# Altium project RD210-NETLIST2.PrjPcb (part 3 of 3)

## Sheet 10.SchDoc
size 609 x 444 mm
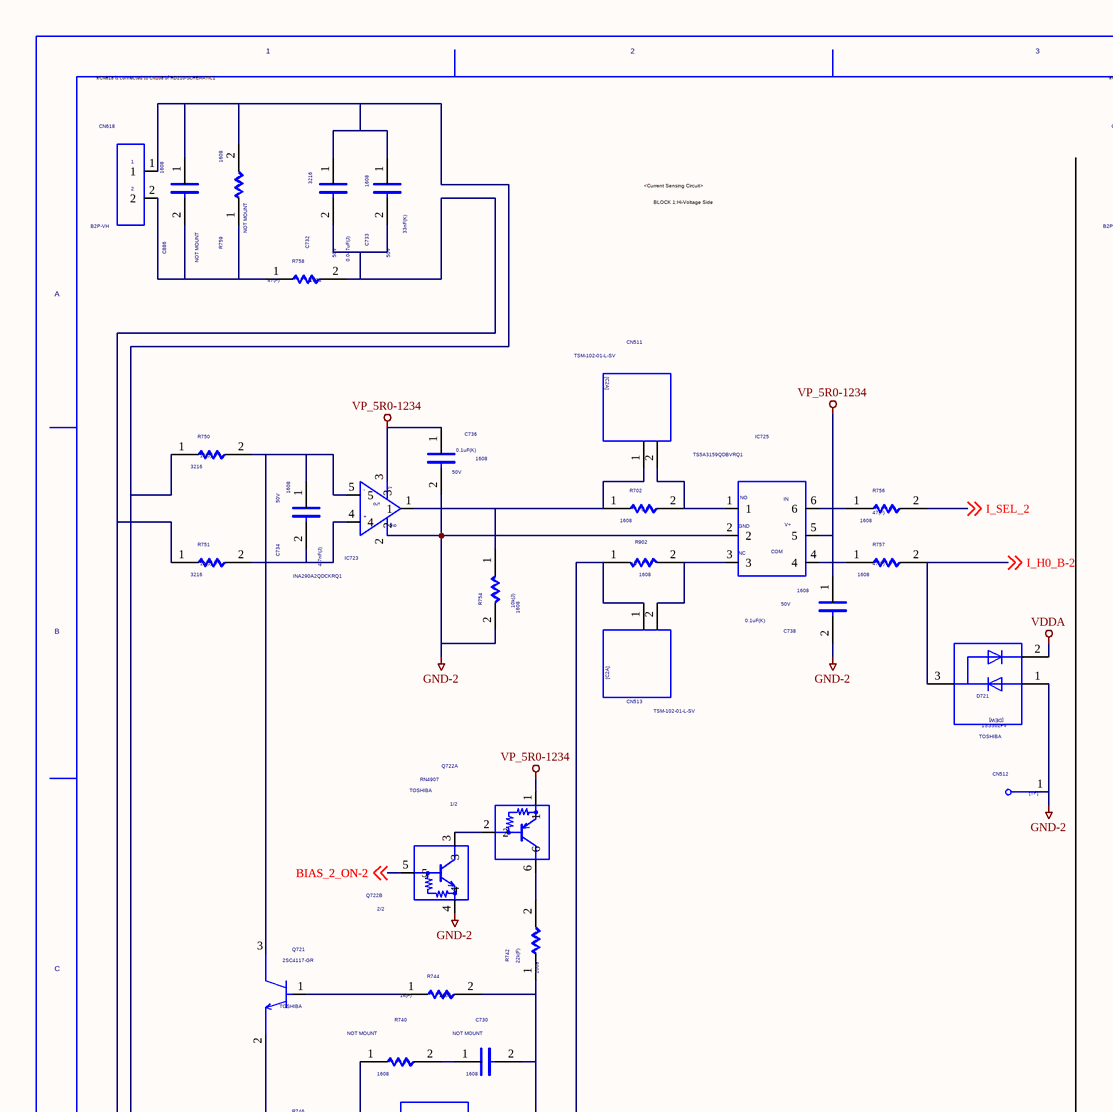
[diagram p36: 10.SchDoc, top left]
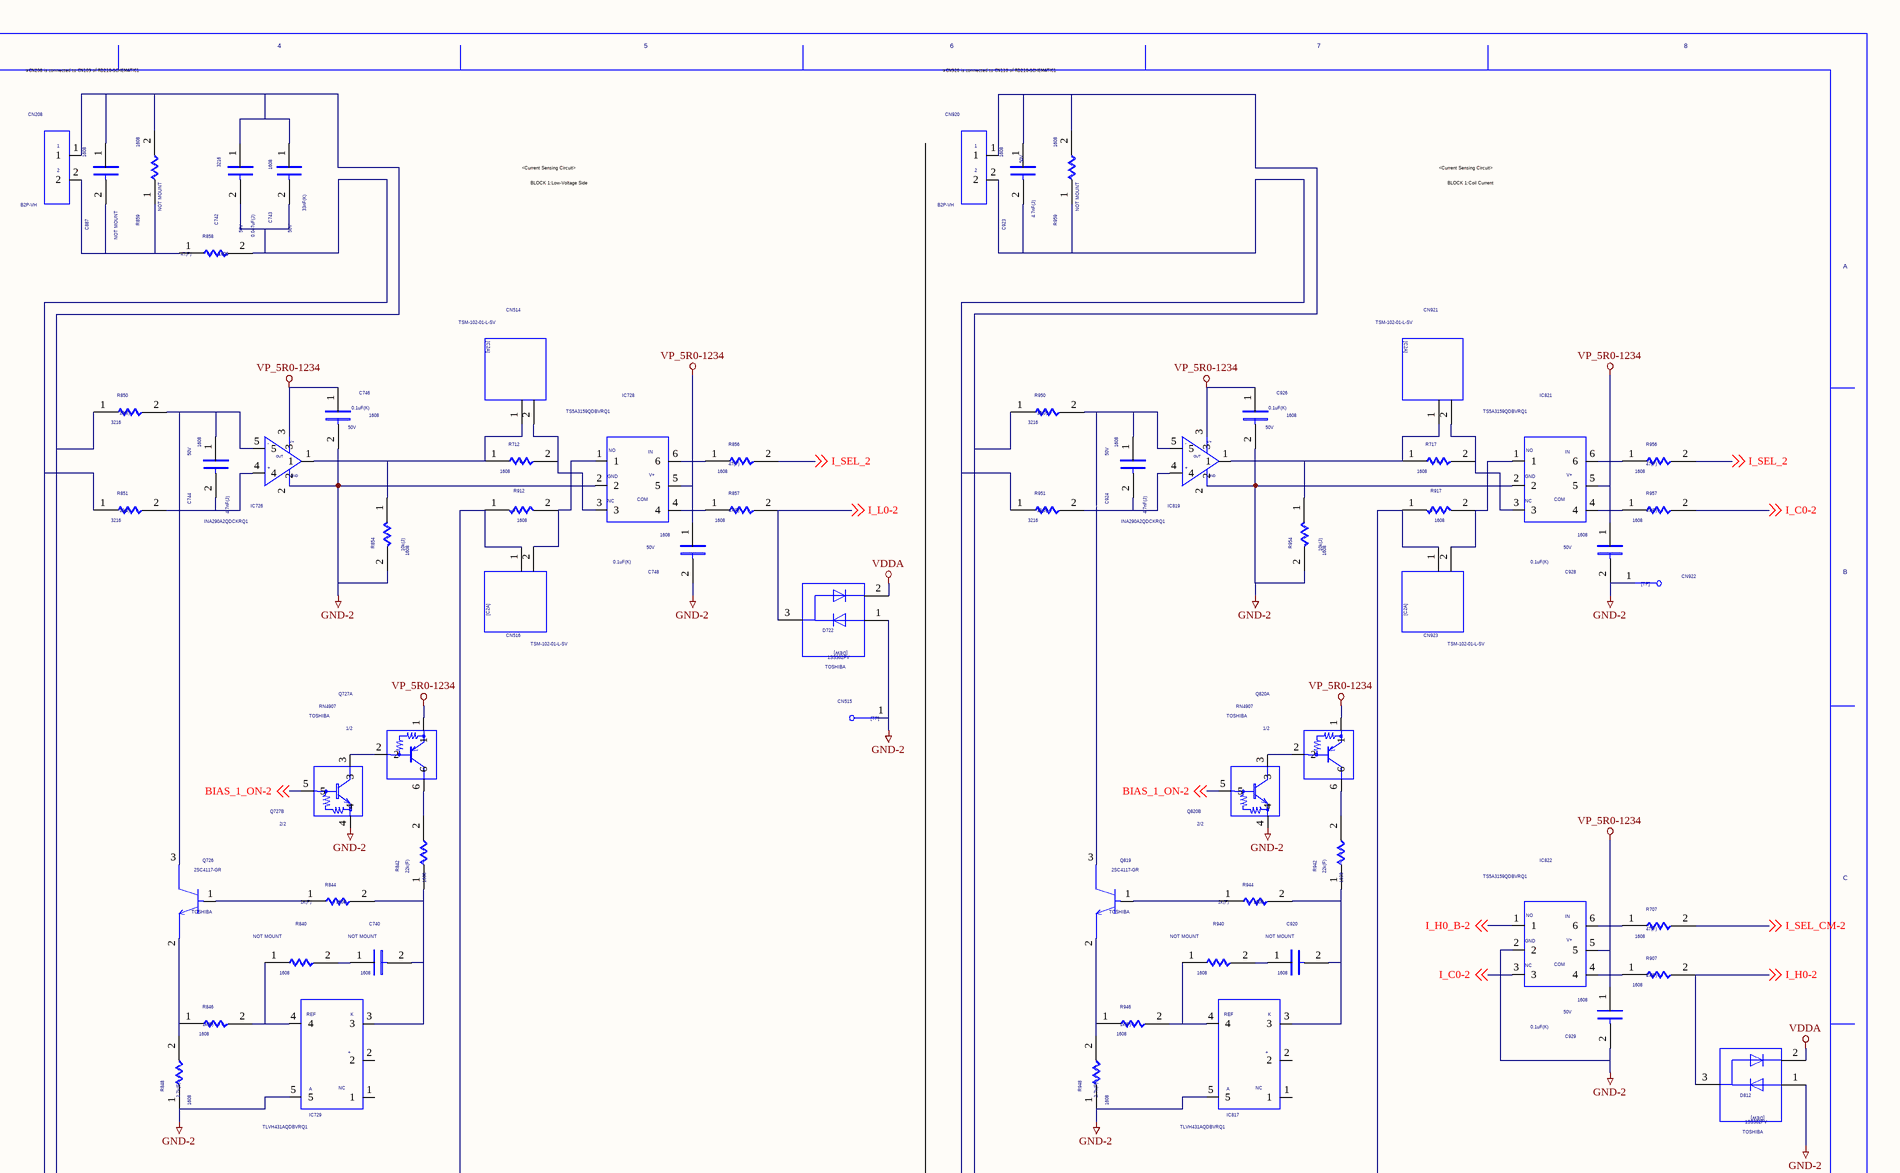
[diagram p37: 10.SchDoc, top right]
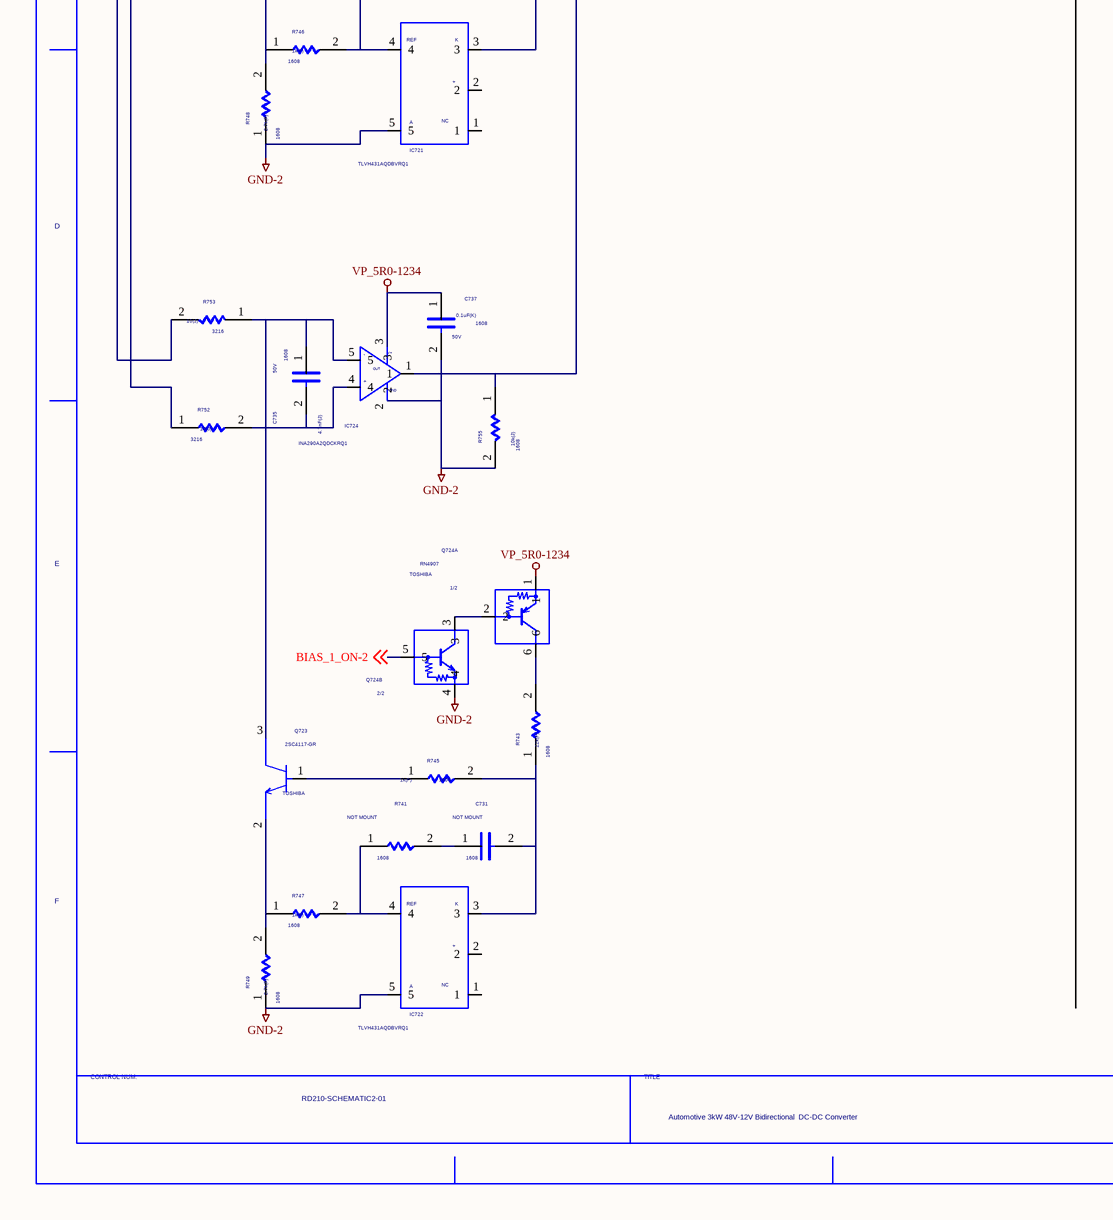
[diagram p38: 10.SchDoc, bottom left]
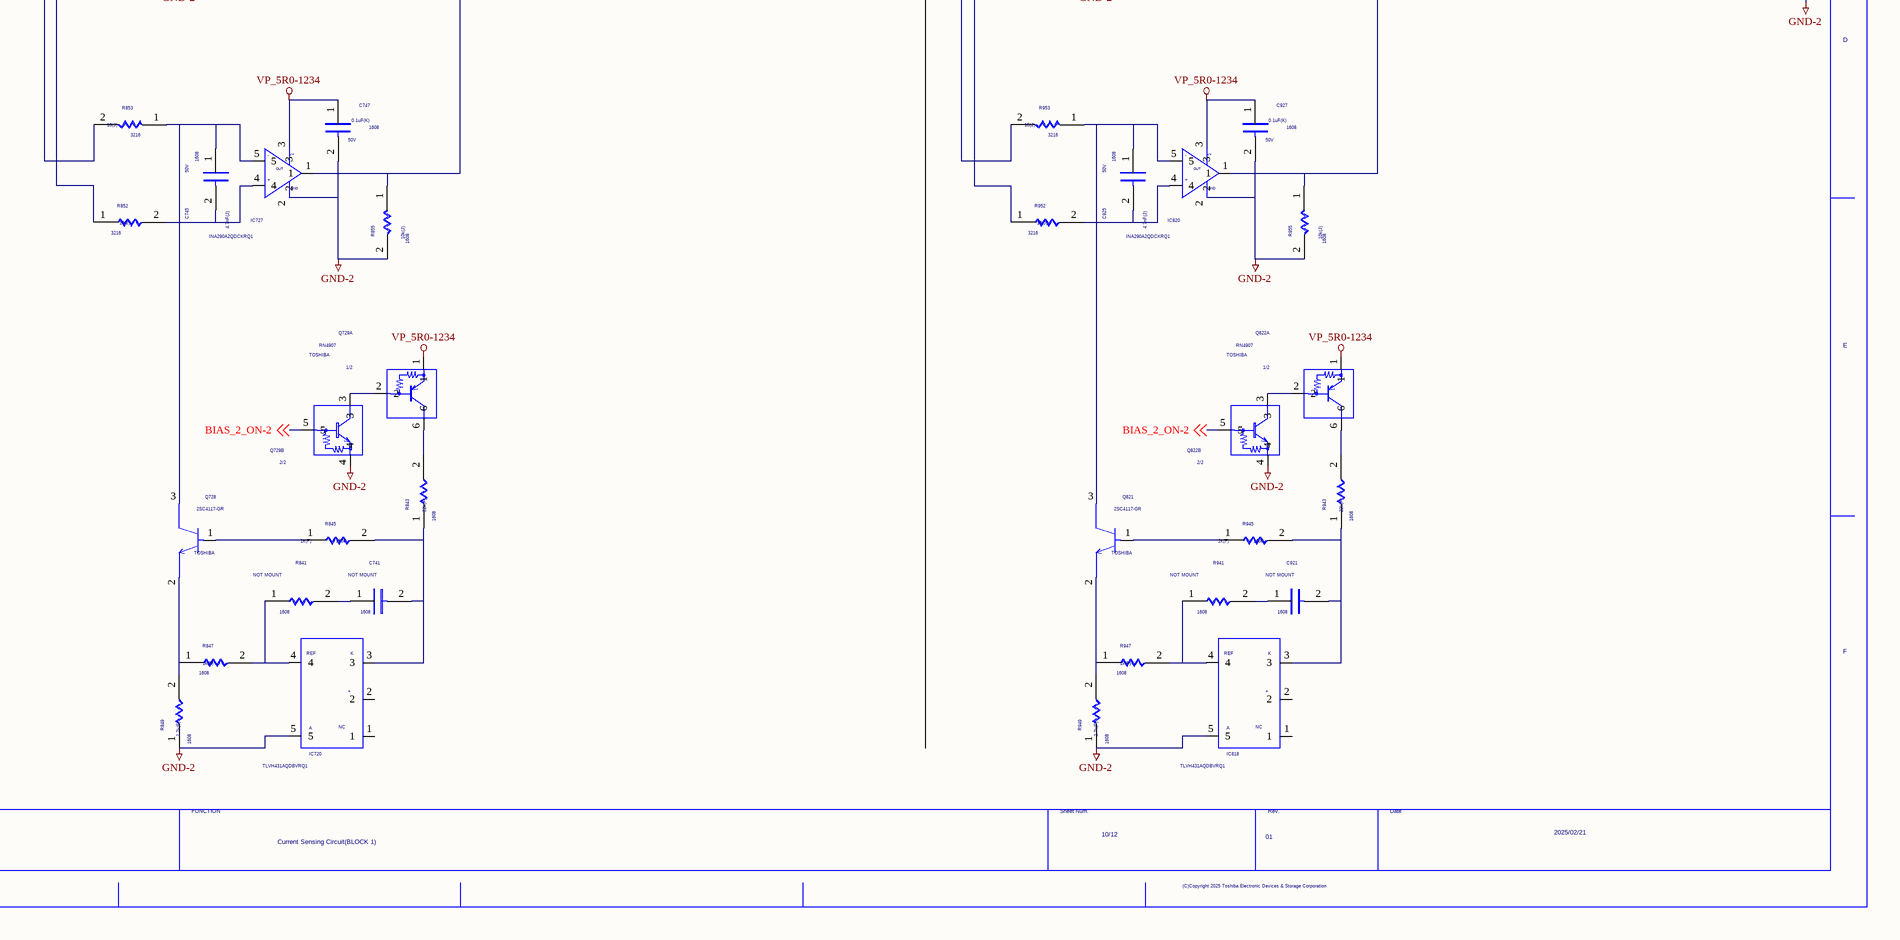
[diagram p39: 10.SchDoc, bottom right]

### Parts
(Parts that share a designator on the sheet are numbered #1, #2 ... from top to bottom, then left to right.)
C730  NOTMOUNT: NOT MOUNT  SIZECODESMD: 1608  (hidden comment: C)
C731  NOTMOUNT: NOT MOUNT  SIZECODESMD: 1608  (hidden comment: C)
C732  VAL1: 0.047uF(J)  VAL2: 50V  SIZECODESMD: 3216  (hidden comment: C)
C733  VAL1: 33nF(K)  VAL2: 50V  SIZECODESMD: 1608  (hidden comment: C)
C734  VAL1: 4.7nF(J)  VAL2: 50V  SIZECODESMD: 1608  (hidden comment: C)
C735  VAL1: 4.7nF(J)  VAL2: 50V  SIZECODESMD: 1608  (hidden comment: C)
C736  VAL1: 0.1uF(K)  VAL2: 50V  SIZECODESMD: 1608  (hidden comment: C)
C737  VAL1: 0.1uF(K)  VAL2: 50V  SIZECODESMD: 1608  (hidden comment: C)
C738  VAL1: 0.1uF(K)  VAL2: 50V  SIZECODESMD: 1608  (hidden comment: C)
C740  NOTMOUNT: NOT MOUNT  SIZECODESMD: 1608  (hidden comment: C)
C741  NOTMOUNT: NOT MOUNT  SIZECODESMD: 1608  (hidden comment: C)
C742  VAL1: 0.047uF(J)  VAL2: 50V  SIZECODESMD: 3216  (hidden comment: C)
C743  VAL1: 33nF(K)  VAL2: 50V  SIZECODESMD: 1608  (hidden comment: C)
C744  VAL1: 4.7nF(J)  VAL2: 50V  SIZECODESMD: 1608  (hidden comment: C)
C745  VAL1: 4.7nF(J)  VAL2: 50V  SIZECODESMD: 1608  (hidden comment: C)
C746  VAL1: 0.1uF(K)  VAL2: 50V  SIZECODESMD: 1608  (hidden comment: C)
C747  VAL1: 0.1uF(K)  VAL2: 50V  SIZECODESMD: 1608  (hidden comment: C)
C748  VAL1: 0.1uF(K)  VAL2: 50V  SIZECODESMD: 1608  (hidden comment: C)
C886  NOTMOUNT: NOT MOUNT  SIZECODESMD: 1608  (hidden comment: C)
C887  NOTMOUNT: NOT MOUNT  SIZECODESMD: 1608  (hidden comment: C)
C920  NOTMOUNT: NOT MOUNT  SIZECODESMD: 1608  (hidden comment: C)
C921  NOTMOUNT: NOT MOUNT  SIZECODESMD: 1608  (hidden comment: C)
C923  VAL1: 4.7nF(J)  VAL2: 50V  SIZECODESMD: 1608  (hidden comment: C)
C924  VAL1: 4.7nF(J)  VAL2: 50V  SIZECODESMD: 1608  (hidden comment: C)
C925  VAL1: 4.7nF(J)  VAL2: 50V  SIZECODESMD: 1608  (hidden comment: C)
C926  VAL1: 0.1uF(K)  VAL2: 50V  SIZECODESMD: 1608  (hidden comment: C)
C927  VAL1: 0.1uF(K)  VAL2: 50V  SIZECODESMD: 1608  (hidden comment: C)
C928  VAL1: 0.1uF(K)  VAL2: 50V  SIZECODESMD: 1608  (hidden comment: C)
C929  VAL1: 0.1uF(K)  VAL2: 50V  SIZECODESMD: 1608  (hidden comment: C)
CN208  B2P-VH
CN511  VAL3: TSM-102-01-L-SV  (hidden comment: C2A)
CN512  TP  (value not drawn)
CN513  VAL3: TSM-102-01-L-SV  (hidden comment: C2A)
CN514  VAL3: TSM-102-01-L-SV  (hidden comment: C2A)
CN515  TP  (value not drawn)
CN516  VAL3: TSM-102-01-L-SV  (hidden comment: C2A)
CN618  B2P-VH
CN920  B2P-VH
CN921  VAL3: TSM-102-01-L-SV  (hidden comment: C2A)
CN922  TP  (value not drawn)
CN923  VAL3: TSM-102-01-L-SV  (hidden comment: C2A)
D721  USERCOMPTEXT3: TOSHIBA  VAL3: 1SS362FV  (hidden comment: DEW)
D722  USERCOMPTEXT3: TOSHIBA  VAL3: 1SS362FV  (hidden comment: DEW)
D812  USERCOMPTEXT3: TOSHIBA  VAL3: 1SS362FV  (hidden comment: DEW)
IC720  TLVH431AQDBVRQ1
IC721  TLVH431AQDBVRQ1
IC722  TLVH431AQDBVRQ1
IC723  INA290A2QDCKRQ1
IC724  INA290A2QDCKRQ1
IC725  TS5A3159QDBVRQ1
IC726  INA290A2QDCKRQ1
IC727  INA290A2QDCKRQ1
IC728  TS5A3159QDBVRQ1
IC729  TLVH431AQDBVRQ1
IC817  TLVH431AQDBVRQ1
IC818  TLVH431AQDBVRQ1
IC819  INA290A2QDCKRQ1
IC820  INA290A2QDCKRQ1
IC821  TS5A3159QDBVRQ1
IC822  TS5A3159QDBVRQ1
Q721  USERCOMPTEXT3: TOSHIBA  VAL3: 2SC4117-GR  (hidden comment: TRN)
Q722  USERCOMPTEXT1: 1/2  USERCOMPTEXT3: TOSHIBA  VAL3: RN4907  (hidden comment: RN4907_Q2)  (parts A,B of 2)
Q723  USERCOMPTEXT3: TOSHIBA  VAL3: 2SC4117-GR  (hidden comment: TRN)
Q724  USERCOMPTEXT1: 1/2  USERCOMPTEXT3: TOSHIBA  VAL3: RN4907  (hidden comment: RN4907_Q2)  (parts A,B of 2)
Q726  USERCOMPTEXT3: TOSHIBA  VAL3: 2SC4117-GR  (hidden comment: TRN)
Q727  USERCOMPTEXT1: 1/2  USERCOMPTEXT3: TOSHIBA  VAL3: RN4907  (hidden comment: RN4907_Q2)  (parts A,B of 2)
Q728  USERCOMPTEXT3: TOSHIBA  VAL3: 2SC4117-GR  (hidden comment: TRN)
Q729  USERCOMPTEXT1: 1/2  USERCOMPTEXT3: TOSHIBA  VAL3: RN4907  (hidden comment: RN4907_Q2)  (parts A,B of 2)
Q819  USERCOMPTEXT3: TOSHIBA  VAL3: 2SC4117-GR  (hidden comment: TRN)
Q820  USERCOMPTEXT1: 1/2  USERCOMPTEXT3: TOSHIBA  VAL3: RN4907  (hidden comment: RN4907_Q2)  (parts A,B of 2)
Q821  USERCOMPTEXT3: TOSHIBA  VAL3: 2SC4117-GR  (hidden comment: TRN)
Q822  USERCOMPTEXT1: 1/2  USERCOMPTEXT3: TOSHIBA  VAL3: RN4907  (hidden comment: RN4907_Q2)  (parts A,B of 2)
R702  VAL1: 0  SIZECODESMD: 1608  (hidden comment: R)
R707  VAL1: 47(F)  SIZECODESMD: 1608  (hidden comment: R)
R712  VAL1: 0  SIZECODESMD: 1608  (hidden comment: R)
R717  VAL1: 0  SIZECODESMD: 1608  (hidden comment: R)
R740  NOTMOUNT: NOT MOUNT  SIZECODESMD: 1608  (hidden comment: R)
R741  NOTMOUNT: NOT MOUNT  SIZECODESMD: 1608  (hidden comment: R)
R742  VAL1: 22k(F)  SIZECODESMD: 1608  (hidden comment: R)
R743  VAL1: 22k(F)  SIZECODESMD: 1608  (hidden comment: R)
R744  VAL1: 1k(F)  SIZECODESMD: 1608  (hidden comment: R)
R745  VAL1: 1k(F)  SIZECODESMD: 1608  (hidden comment: R)
R746  VAL1: 1k(F)  SIZECODESMD: 1608  (hidden comment: R)
R747  VAL1: 1k(F)  SIZECODESMD: 1608  (hidden comment: R)
R748  VAL1: 2.7k(F)  SIZECODESMD: 1608  (hidden comment: R)
R749  VAL1: 2.7k(F)  SIZECODESMD: 1608  (hidden comment: R)
R750  VAL1: 10(J)  SIZECODESMD: 3216  (hidden comment: R)
R751  VAL1: 10(J)  SIZECODESMD: 3216  (hidden comment: R)
R752  VAL1: 10(J)  SIZECODESMD: 3216  (hidden comment: R)
R753  VAL1: 10(J)  SIZECODESMD: 3216  (hidden comment: R)
R754  VAL1: 10k(J)  SIZECODESMD: 1608  (hidden comment: R)
R755  VAL1: 10k(J)  SIZECODESMD: 1608  (hidden comment: R)
R756  VAL1: 47(F)  SIZECODESMD: 1608  (hidden comment: R)
R757  VAL1: 47(F)  SIZECODESMD: 1608  (hidden comment: R)
R758  VAL1: 47(F)  SIZECODESMD: 1608  (hidden comment: R)
R759  NOTMOUNT: NOT MOUNT  SIZECODESMD: 1608  (hidden comment: R)
R840  NOTMOUNT: NOT MOUNT  SIZECODESMD: 1608  (hidden comment: R)
R841  NOTMOUNT: NOT MOUNT  SIZECODESMD: 1608  (hidden comment: R)
R842  VAL1: 22k(F)  SIZECODESMD: 1608  (hidden comment: R)
R843  VAL1: 22k(F)  SIZECODESMD: 1608  (hidden comment: R)
R844  VAL1: 1k(F)  SIZECODESMD: 1608  (hidden comment: R)
R845  VAL1: 1k(F)  SIZECODESMD: 1608  (hidden comment: R)
R846  VAL1: 1k(F)  SIZECODESMD: 1608  (hidden comment: R)
R847  VAL1: 1k(F)  SIZECODESMD: 1608  (hidden comment: R)
R848  VAL1: 2.7k(F)  SIZECODESMD: 1608  (hidden comment: R)
R849  VAL1: 2.7k(F)  SIZECODESMD: 1608  (hidden comment: R)
R850  VAL1: 10(J)  SIZECODESMD: 3216  (hidden comment: R)
R851  VAL1: 10(J)  SIZECODESMD: 3216  (hidden comment: R)
R852  VAL1: 10(J)  SIZECODESMD: 3216  (hidden comment: R)
R853  VAL1: 10(J)  SIZECODESMD: 3216  (hidden comment: R)
R854  VAL1: 10k(J)  SIZECODESMD: 1608  (hidden comment: R)
R855  VAL1: 10k(J)  SIZECODESMD: 1608  (hidden comment: R)
R856  VAL1: 47(F)  SIZECODESMD: 1608  (hidden comment: R)
R857  VAL1: 47(F)  SIZECODESMD: 1608  (hidden comment: R)
R858  VAL1: 47(F)  SIZECODESMD: 1608  (hidden comment: R)
R859  NOTMOUNT: NOT MOUNT  SIZECODESMD: 1608  (hidden comment: R)
R902  VAL1: 0  SIZECODESMD: 1608  (hidden comment: R)
R907  VAL1: 47(F)  SIZECODESMD: 1608  (hidden comment: R)
R912  VAL1: 0  SIZECODESMD: 1608  (hidden comment: R)
R917  VAL1: 0  SIZECODESMD: 1608  (hidden comment: R)
R940  NOTMOUNT: NOT MOUNT  SIZECODESMD: 1608  (hidden comment: R)
R941  NOTMOUNT: NOT MOUNT  SIZECODESMD: 1608  (hidden comment: R)
R942  VAL1: 22k(F)  SIZECODESMD: 1608  (hidden comment: R)
R943  VAL1: 22k(F)  SIZECODESMD: 1608  (hidden comment: R)
R944  VAL1: 1k(F)  SIZECODESMD: 1608  (hidden comment: R)
R945  VAL1: 1k(F)  SIZECODESMD: 1608  (hidden comment: R)
R946  VAL1: 1k(F)  SIZECODESMD: 1608  (hidden comment: R)
R947  VAL1: 1k(F)  SIZECODESMD: 1608  (hidden comment: R)
R948  VAL1: 2.7k(F)  SIZECODESMD: 1608  (hidden comment: R)
R949  VAL1: 2.7k(F)  SIZECODESMD: 1608  (hidden comment: R)
R950  VAL1: 10(J)  SIZECODESMD: 3216  (hidden comment: R)
R951  VAL1: 10(J)  SIZECODESMD: 3216  (hidden comment: R)
R952  VAL1: 10(J)  SIZECODESMD: 3216  (hidden comment: R)
R953  VAL1: 10(J)  SIZECODESMD: 3216  (hidden comment: R)
R954  VAL1: 10k(J)  SIZECODESMD: 1608  (hidden comment: R)
R955  VAL1: 10k(J)  SIZECODESMD: 1608  (hidden comment: R)
R956  VAL1: 47(F)  SIZECODESMD: 1608  (hidden comment: R)
R957  VAL1: 47(F)  SIZECODESMD: 1608  (hidden comment: R)
R959  NOTMOUNT: NOT MOUNT  SIZECODESMD: 1608  (hidden comment: R)
U?#10  DATE: 2025/02/21  DRAWINGNUMBER: RD210-SCHEMATIC2-01  TITLE: Automotive 3kW 48V-12V Bidirectional / DC-DC Converter  FUNCTION: Current Sensing Circuit(BLOCK 1)  SHEETNUMBER: 10/12  REVISION: 01  (hidden comment: WAKU_DEF_A3)

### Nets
GND-2: C736.2 C737.2 C738.2 C746.2 C747.2 C748.2 C926.2 C927.2 C928.2 C929.2 CN512.1 CN515.1 CN922.1 D721.1(A) D722.1(A) D812.1(A) IC720.5 IC721.5 IC722.5 IC723.2 IC724.2 IC725.2 IC726.2 IC727.2 IC728.2 IC729.5 IC817.5 IC818.5 IC819.2 IC820.2 IC821.2 IC822.2 Q722.4 Q724.4 Q727.4 Q729.4 Q820.4 Q822.4 R748.1 R749.1 R754.2 R755.2 R848.1 R849.1 R854.2 R855.2 R948.1 R949.1 R954.2 R955.2
VDDA: D721.2(C) D722.2(C) D812.2(C)
VP_5R0-1234: C736.1 C737.1 C738.1 C746.1 C747.1 C748.1 C926.1 C927.1 C928.1 C929.1 IC723.3 IC724.3 IC725.5 IC726.3 IC727.3 IC728.5 IC819.3 IC820.3 IC821.5 IC822.5 Q722.1 Q724.1 Q727.1 Q729.1 Q820.1 Q822.1
BIAS_1_ON-2: Q724.5 Q727.5 Q820.5 ; off-sheet BIAS_1_ON-2
BIAS_2_ON-2: Q722.5 Q729.5 Q822.5 ; off-sheet BIAS_2_ON-2
I_C0-2: IC822.3 R957.2 ; off-sheet I_C0-2
I_H0-2: D812.3(AC) R907.2 ; off-sheet I_H0-2
I_H0_B-2: D721.3(AC) IC822.1 R757.2 ; off-sheet I_H0_B-2
I_L0-2: D722.3(AC) R857.2 ; off-sheet I_L0-2
I_SEL_2: R756.2 R856.2 R956.2 ; off-sheet I_SEL_2
I_SEL_CM-2: R707.2 ; off-sheet I_SEL_CM-2
SIG0101: CN513.2 IC725.3 R902.2
SIG0102: Q721.1(B) R744.1
SIG0103: C730.1 R740.2
SIG0104: C735.2 IC724.4 R752.2
SIG0105: C734.2 IC723.4 R751.2
SIG0106: CN511.2 IC725.1 R702.2
SIG0107: IC725.4 R757.1
SIG0108: IC725.6 R756.1
SIG0109: IC721.4 R740.1 R746.2
SIG01010: Q722.6 R742.2
SIG01011: CN511.1 IC723.1 R702.1 R754.1
SIG01012: CN513.1 IC724.1 R755.1 R902.1
SIG01013: C730.2 IC721.3 R742.1 R744.2
SIG01014: Q721.2(E) R746.1 R748.2
SIG01015: Q722.2 Q722.3
SIG01016: Q724.2 Q724.3
SIG01017: C731.2 IC722.3 R743.1 R745.2
SIG01018: IC722.4 R741.1 R747.2
SIG01019: C731.1 R741.2
SIG01020: Q724.6 R743.2
SIG01021: Q723.2(E) R747.1 R749.2
SIG01022: Q723.1(B) R745.1
SIG01023: C735.1 IC724.5 Q723.3(C) R753.1
SIG01024: C734.1 IC723.5 Q721.3(C) R750.2
SIG01025: C886.2 CN618.2 R758.1 R759.1
SIG01026: C732.2 C733.2 R751.1 R753.2 R758.2
SIG01027: C732.1 C733.1 C886.1 CN618.1 R750.1 R752.1 R759.2
SIG01028: CN514.1 IC726.1 R712.1 R854.1
SIG01029: IC728.6 R856.1
SIG01030: C741.2 IC720.3 R843.1 R845.2
SIG01031: IC728.4 R857.1
SIG01032: C740.1 R840.2
SIG01033: C745.1 IC727.5 Q728.3(C) R853.1
SIG01034: C744.2 IC726.4 R851.2
SIG01035: CN516.1 IC727.1 R855.1 R912.1
SIG01036: Q726.1(B) R844.1
SIG01037: Q728.1(B) R845.1
SIG01038: Q729.6 R843.2
SIG01039: C741.1 R841.2
SIG01040: IC720.4 R841.1 R847.2
SIG01041: C745.2 IC727.4 R852.2
SIG01042: Q726.2(E) R846.1 R848.2
SIG01043: Q727.2 Q727.3
SIG01044: C740.2 IC729.3 R842.1 R844.2
SIG01045: Q729.2 Q729.3
SIG01046: C742.2 C743.2 R851.1 R853.2 R858.2
SIG01047: Q728.2(E) R847.1 R849.2
SIG01048: C887.2 CN208.2 R858.1 R859.1
SIG01049: C744.1 IC726.5 Q726.3(C) R850.2
SIG01050: Q727.6 R842.2
SIG01051: IC729.4 R840.1 R846.2
SIG01052: C742.1 C743.1 C887.1 CN208.1 R850.1 R852.1 R859.2
SIG01053: CN516.2 IC728.1 R912.2
SIG01054: CN514.2 IC728.3 R712.2
SIG01055: Q820.2 Q820.3
SIG01056: C920.2 IC817.3 R942.1 R944.2
SIG01057: CN921.2 IC821.3 R717.2
SIG01058: C923.1 CN920.1 R950.1 R952.1 R959.2
SIG01059: Q822.2 Q822.3
SIG01060: C924.1 IC819.5 Q819.3(C) R950.2
SIG01061: Q819.2(E) R946.1 R948.2
SIG01062: Q821.2(E) R947.1 R949.2
SIG01063: Q820.6 R942.2
SIG01064: CN923.2 IC821.1 R917.2
SIG01065: IC817.4 R940.1 R946.2
SIG01066: C925.2 IC820.4 R952.2
SIG01067: C921.1 R941.2
SIG01068: Q821.1(B) R945.1
SIG01069: Q819.1(B) R944.1
SIG01070: CN923.1 IC820.1 R917.1 R955.1
SIG01071: IC818.4 R941.1 R947.2
SIG01072: Q822.6 R943.2
SIG01073: CN921.1 IC819.1 R717.1 R954.1
SIG01074: C924.2 IC819.4 R951.2
SIG01075: IC821.4 R957.1
SIG01076: C925.1 IC820.5 Q821.3(C) R953.1
SIG01077: IC821.6 R956.1
SIG01078: C921.2 IC818.3 R943.1 R945.2
SIG01079: C920.1 R940.2
SIG01080: C923.2 CN920.2 R951.1 R953.2 R959.1
SIG01081: IC822.4 R907.1
SIG01082: IC822.6 R707.1

Not connected (* = marked no-connect by the designer): IC720 1 2; IC721 1 2; IC722 1 2; IC729 1 2; IC817 1 2; IC818 1 2

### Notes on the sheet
- ※CN618 is connected to CN108 of RD210-SCHEMATIC1
- ※CN208 is connected to CN109 of RD210-SCHEMATIC1
- ※CN920 is connected to CN110 of RD210-SCHEMATIC1
- <Current Sensing Circuit>
- BLOCK 1:Hi-Voltage Side
- BLOCK 1:Low-Voltage Side
- BLOCK 1:Coil Current

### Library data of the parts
C730 C731 C740 C741 C920 C921 = C: VAL1: 0.1uF(K); VAL2: 50V; OriginalSymbolOrigin: (2540,7620)
C732-C738 C742-C748 C923-C929 = C: OriginalSymbolOrigin: (2540,7620)
C886 C887 = C: VAL1: 4.7nF(J); VAL2: 50V; OriginalSymbolOrigin: (2540,7620)
CN208 CN618 CN920 = B2P-VH: MANUFACTURER: PHOENIX CONTACT; ITEM: Connector 2Pin Terminal Block; SCH_NAME: MCV1,5/2-G-3.5; TIME: 08:44:48; UPDATEUSER: sptcae13; UPDATETIME: 17:31:47; SAVECOUNT: 5; SAVEAREA0: -87042,-47887,89765,32676; OriginalSymbolOrigin: (0,0); CDBNAME: CN
CN511 CN513 CN514 CN516 CN921 CN923 = C2A: SAVEAREA0: -4611,-206,24632,18258; SAVECOUNT: 25; TIME: 13:28:28; UPDATEUSER: tomizawa-y; UPDATETIME: 12:08:31; OriginalSymbolOrigin: (2540,15240); CDBNAME: CN
CN512 CN515 CN922 = TP: TIME: 16:12:21; UPDATEUSER: fukuda-y; UPDATETIME: 16:18:11; SAVECOUNT: 2; SAVEAREA0: -242,-92,12810,7836; OriginalSymbolOrigin: (0,7620); VAL3: TSW-101-07-G-S; CDBNAME: CN
D721 D722 D812 = DEW: SAVEAREA0: -10024,-234,32508,20938; TIME: 14:49:55; UPDATEUSER: 19990028; UPDATETIME: 14:00:58; SAVECOUNT: 4; OriginalSymbolOrigin: (5080,17780); CDBNAME: D
IC720-IC722 IC729 IC817 IC818 = TLVH431AQDBVRQ1: MANUFACTURER: Panasonic; ITEM: Register; SIZECODESMD: 1608; VLUE4: (B); TIME: 08:44:47; UPDATEUSER: sptcae13; UPDATETIME: 17:49:34; SAVECOUNT: 11; SAVEAREA0: -8264,-23317,25334,1279; OriginalSymbolOrigin: (2540,0); CDBNAME: IC
IC723 IC724 IC726 IC727 IC819 IC820 = INA290A2QDCKRQ1: MANUFACTURER: TOSHIBA; ITEM: IC Logic; TIME: 08:44:45; UPDATEUSER: sptcae13; UPDATETIME: 08:56:52; SAVECOUNT: 17; SAVEAREA0: -4733,-13253,17562,3068; OriginalSymbolOrigin: (2540,0); CDBNAME: IC
IC725 IC728 IC821 IC822 = TS5A3159QDBVRQ1: MANUFACTURER: Panasonic; ITEM: Register; SIZECODESMD: 1608; VLUE4: (B); TIME: 08:44:47; UPDATEUSER: sptcae13; UPDATETIME: 19:09:10; SAVECOUNT: 15; SAVEAREA0: -8264,-23317,25334,1279; OriginalSymbolOrigin: (2540,0); CDBNAME: IC
Q721 Q723 Q726 Q728 Q819 Q821 = TRN: TIME: 09:39:04; UPDATEUSER: 19910145; UPDATETIME: 15:12:10; SAVECOUNT: 8; SAVEAREA0: -6194,-158,18648,15662; OriginalSymbolOrigin: (2540,17780); CDBNAME: Q
Q722 Q724 Q727 Q729 Q820 Q822 = RN4907_Q2: 7TH PART FIELD: RES.,; 4TH PART FIELD: VISHAY,; 3RD PART FIELD: CHIP; 2ND PART FIELD: 1-5%; 5TH PART FIELD: CRCW0805---RT6; 1ST PART FIELD: 1/8W; PARTS: 1; VAL1: VALUE; TIME: 08:44:45; UPDATEUSER: t4887876; UPDATETIME: 19:03:09; SAVECOUNT: 13; CLASS: DISCRETE; HETERO: RN4905_1,RN4905_2; FUNCTION: PNP&NPN_PCT; LEVEL: STD; PKG_TYPE: 2-2J1A; DEVICE: RN4905; SAVEAREA0: -13854,-30480,41847,0; DEVICENAME: DTC144EETL; OriginalSymbolOrigin: (0,12700); CaptureCellPackProp: RN4907_Q2A; COMPONENTNAME: RN4907_1
R702 R712 R717 R902 R912 R917 = R: OriginalSymbolOrigin: (5080,5080)
R707 R744-R747 R756-R758 R844-R847 R856-R858 R907 R944-R947 R956 R957 = R: VAL2: 125mW; OriginalSymbolOrigin: (5080,5080)
R740 R741 R840 R841 R940 R941 = R: VAL2: 100mW; VAL1: 1k(F); OriginalSymbolOrigin: (5080,5080)
R742 R743 R748 R749 R754 R755 R842 R843 R848 R849 R854 R855 R942 R943 R948 R949 R954 R955 = R: VAL2: 100mW; OriginalSymbolOrigin: (5080,5080)
R750-R753 R850-R853 R950-R953 = R: VAL2: 250mW; OriginalSymbolOrigin: (5080,5080)
R759 R859 R959 = R: VAL2: 100mW; VAL1: 10(F); OriginalSymbolOrigin: (5080,5080)
U?#10 = WAKU_DEF_A3: PLOTTIME: HH:MM; SAVEAREA0: 96913,-567914,509243,-368858; TIME: 14:30:25; UPDATEUSER: t5459927; UPDATETIME: 06:49:54; SAVECOUNT: 20; ZONEOFFSETX: 36; ZONEOFFSETY: -24; OriginalSymbolOrigin: (12700,-12700); SHTSAVECOUNT: 173

## Sheet 11.SchDoc
size 609 x 444 mm
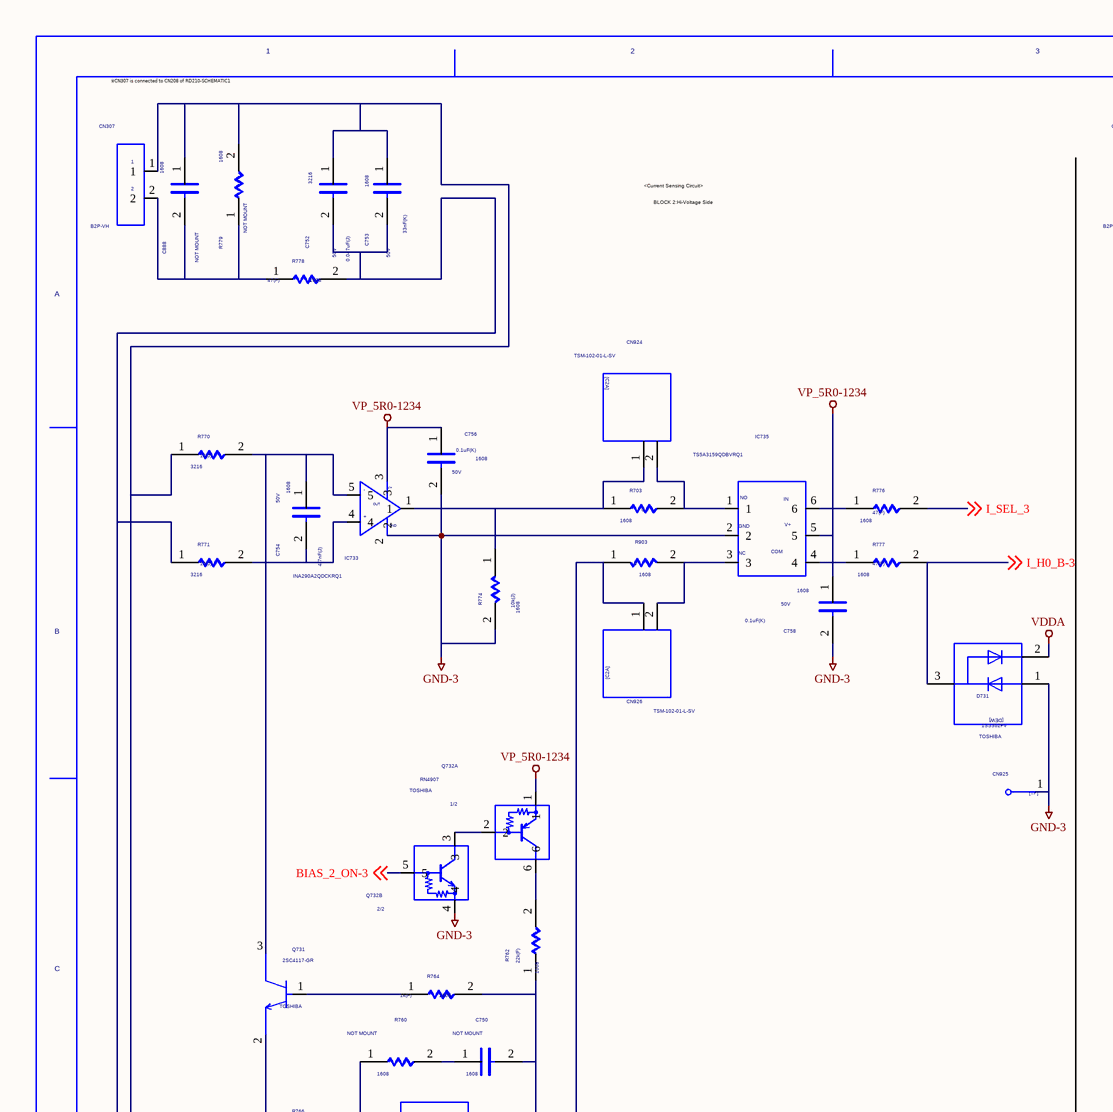
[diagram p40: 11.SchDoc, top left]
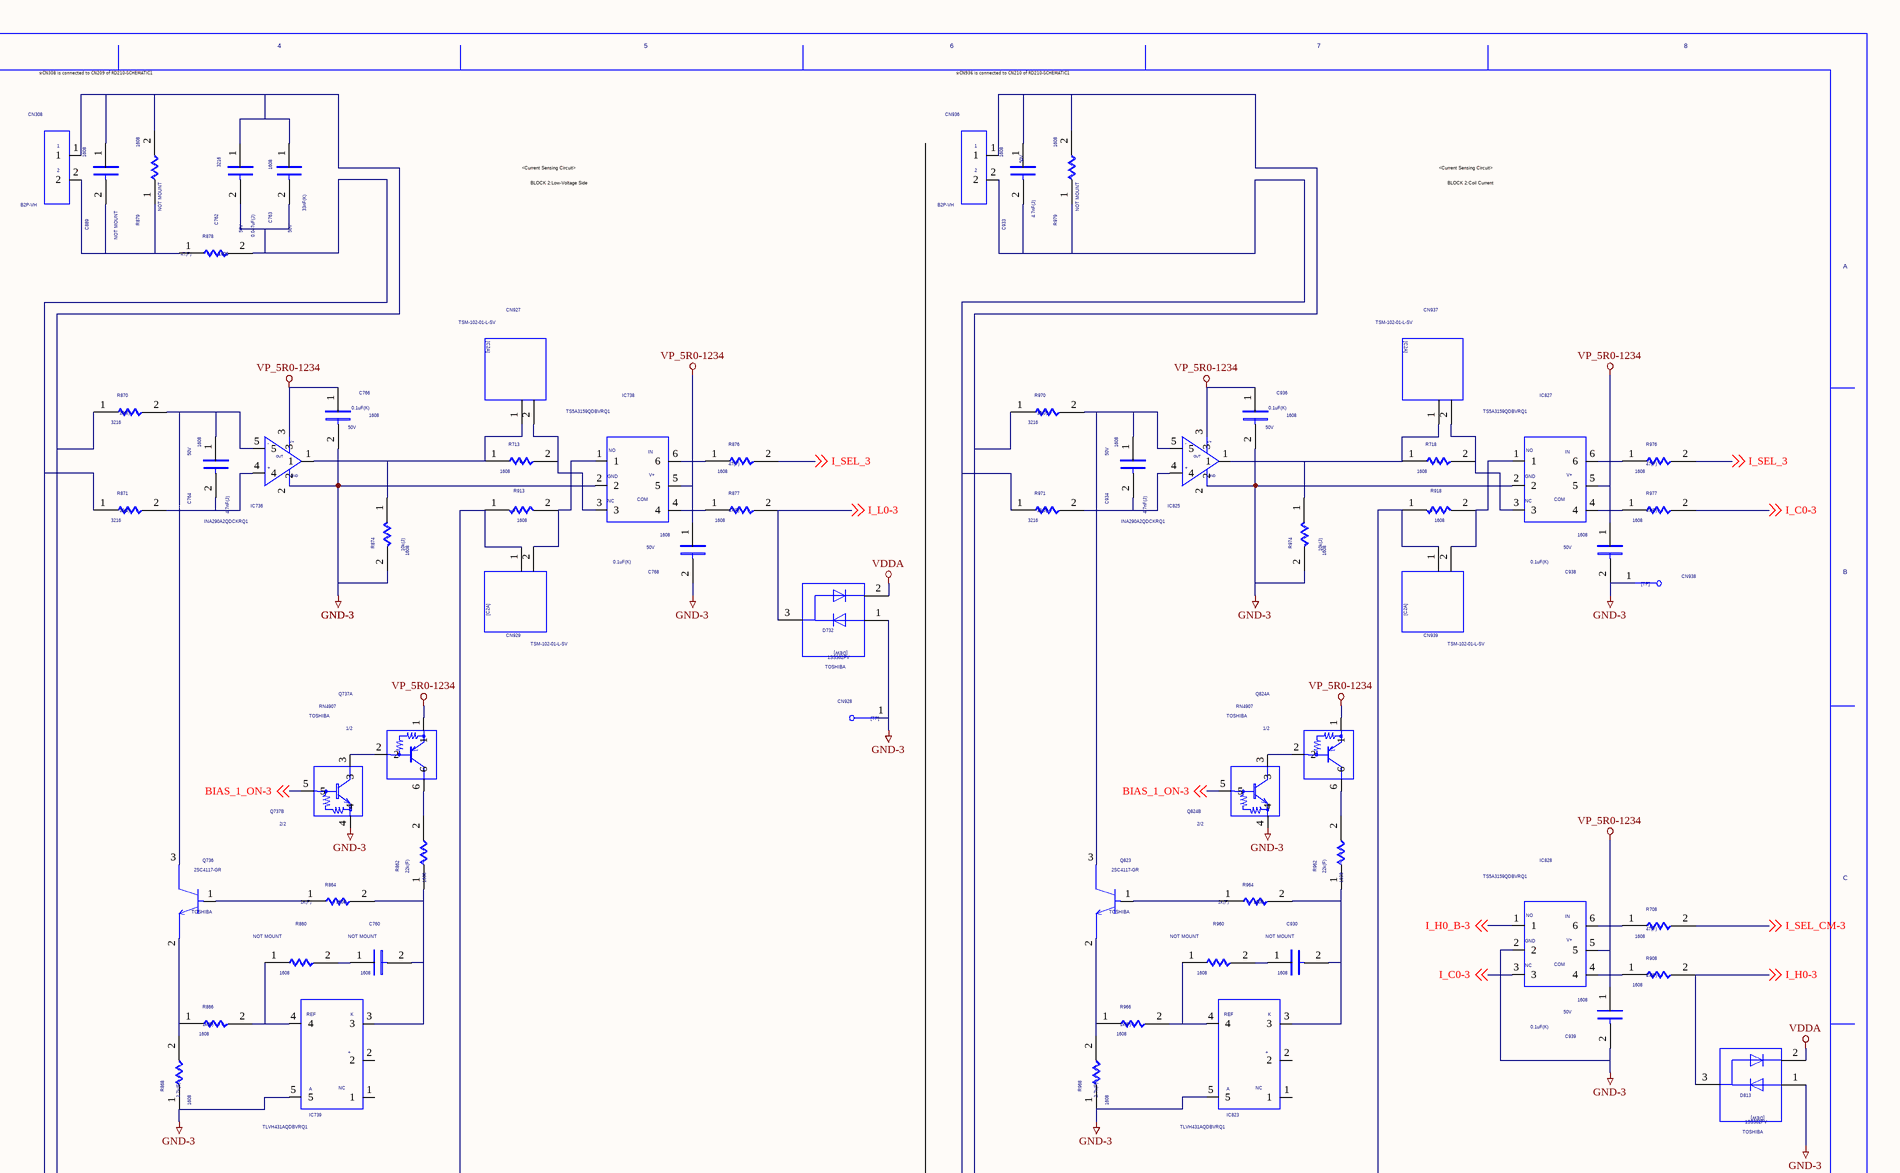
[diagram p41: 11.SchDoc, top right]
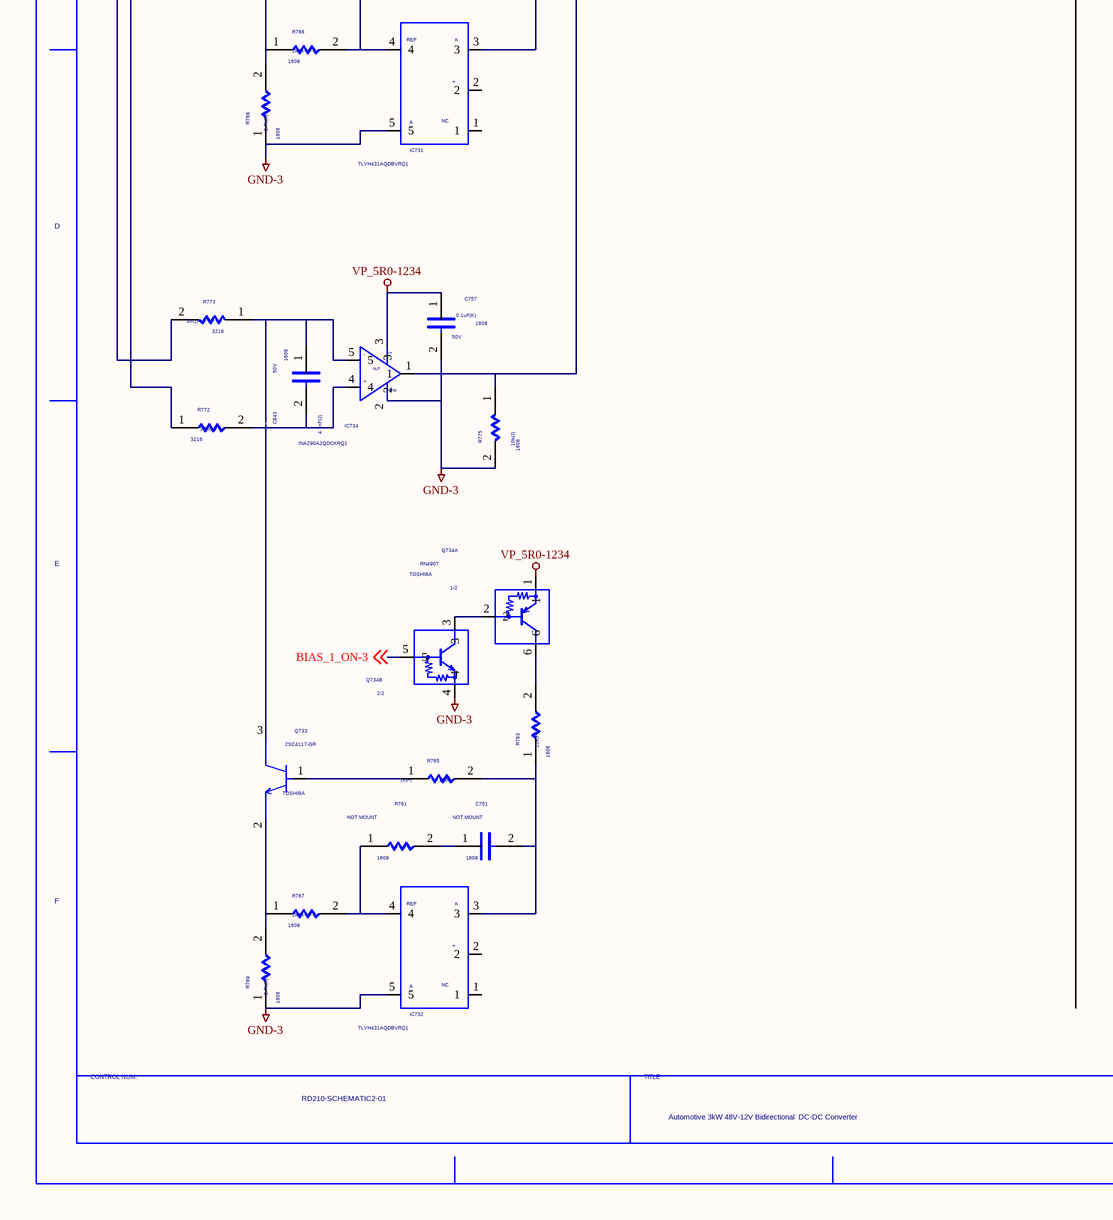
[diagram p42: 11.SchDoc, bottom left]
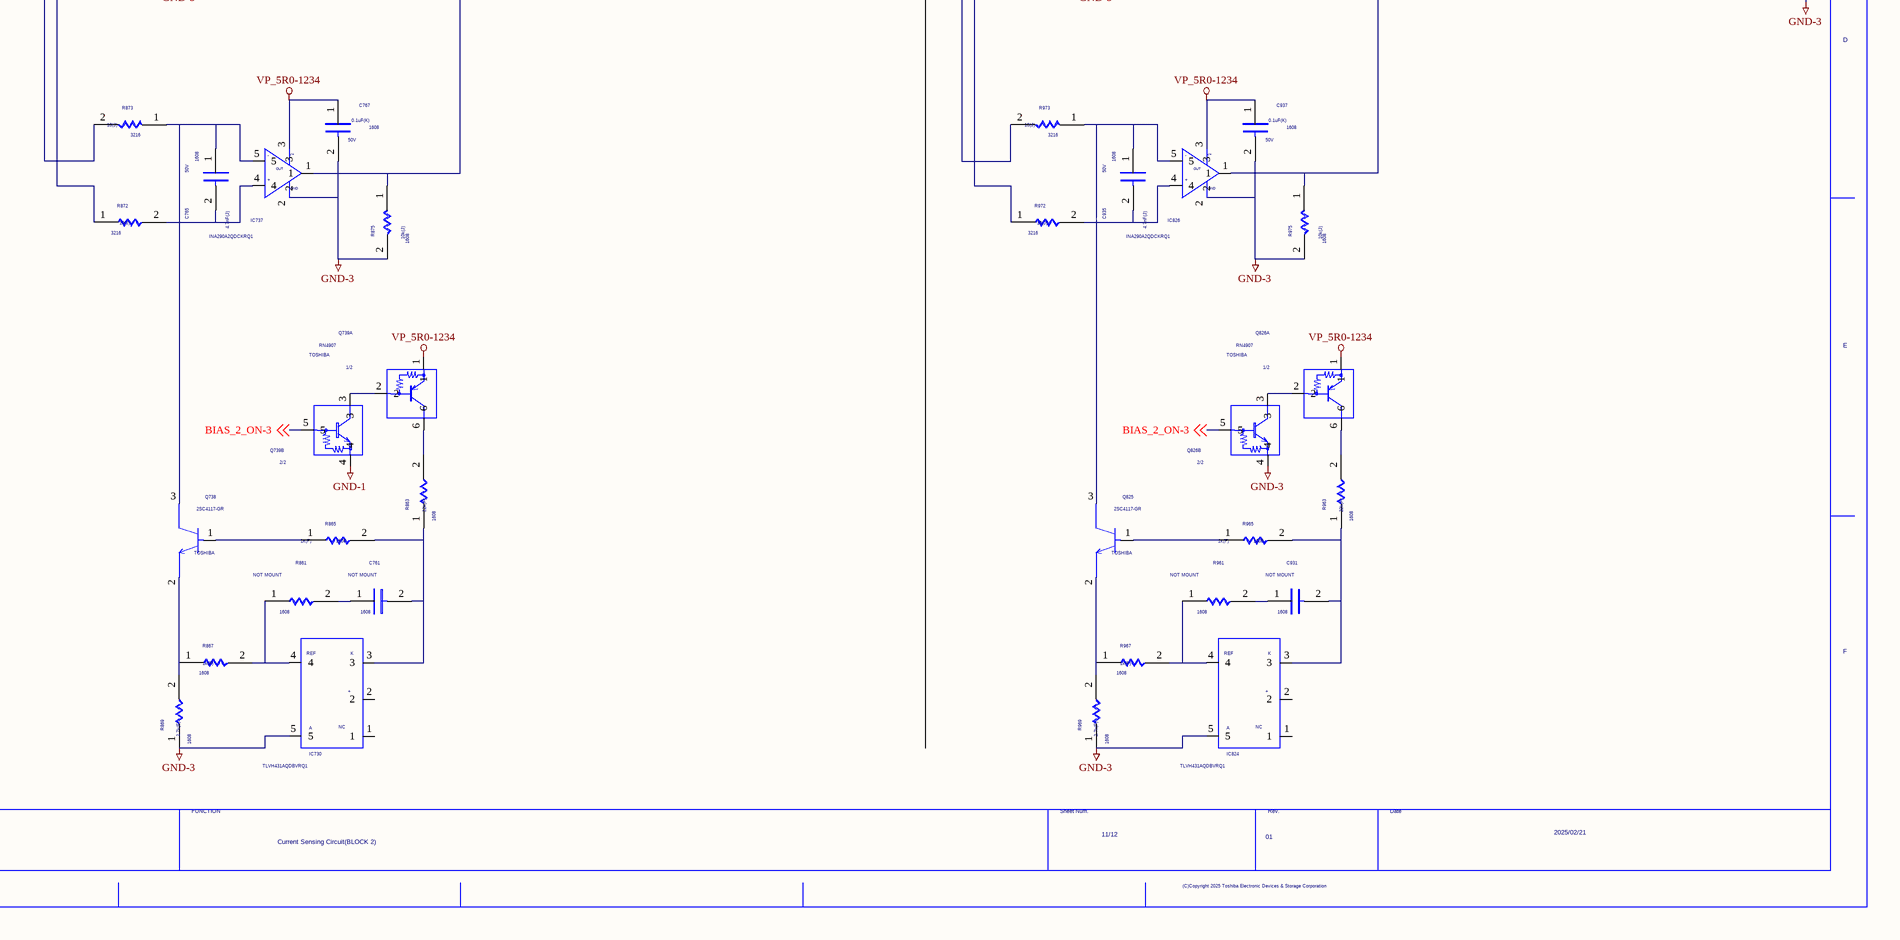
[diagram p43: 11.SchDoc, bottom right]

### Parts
(Parts that share a designator on the sheet are numbered #1, #2 ... from top to bottom, then left to right.)
C750  NOTMOUNT: NOT MOUNT  SIZECODESMD: 1608  (hidden comment: C)
C751  NOTMOUNT: NOT MOUNT  SIZECODESMD: 1608  (hidden comment: C)
C752  VAL1: 0.047uF(J)  VAL2: 50V  SIZECODESMD: 3216  (hidden comment: C)
C753  VAL1: 33nF(K)  VAL2: 50V  SIZECODESMD: 1608  (hidden comment: C)
C754  VAL1: 4.7nF(J)  VAL2: 50V  SIZECODESMD: 1608  (hidden comment: C)
C756  VAL1: 0.1uF(K)  VAL2: 50V  SIZECODESMD: 1608  (hidden comment: C)
C757  VAL1: 0.1uF(K)  VAL2: 50V  SIZECODESMD: 1608  (hidden comment: C)
C758  VAL1: 0.1uF(K)  VAL2: 50V  SIZECODESMD: 1608  (hidden comment: C)
C760  NOTMOUNT: NOT MOUNT  SIZECODESMD: 1608  (hidden comment: C)
C761  NOTMOUNT: NOT MOUNT  SIZECODESMD: 1608  (hidden comment: C)
C762  VAL1: 0.047uF(J)  VAL2: 50V  SIZECODESMD: 3216  (hidden comment: C)
C763  VAL1: 33nF(K)  VAL2: 50V  SIZECODESMD: 1608  (hidden comment: C)
C764  VAL1: 4.7nF(J)  VAL2: 50V  SIZECODESMD: 1608  (hidden comment: C)
C765  VAL1: 4.7nF(J)  VAL2: 50V  SIZECODESMD: 1608  (hidden comment: C)
C766  VAL1: 0.1uF(K)  VAL2: 50V  SIZECODESMD: 1608  (hidden comment: C)
C767  VAL1: 0.1uF(K)  VAL2: 50V  SIZECODESMD: 1608  (hidden comment: C)
C768  VAL1: 0.1uF(K)  VAL2: 50V  SIZECODESMD: 1608  (hidden comment: C)
C843  VAL1: 4.7nF(J)  VAL2: 50V  SIZECODESMD: 1608  (hidden comment: C)
C888  NOTMOUNT: NOT MOUNT  SIZECODESMD: 1608  (hidden comment: C)
C889  NOTMOUNT: NOT MOUNT  SIZECODESMD: 1608  (hidden comment: C)
C930  NOTMOUNT: NOT MOUNT  SIZECODESMD: 1608  (hidden comment: C)
C931  NOTMOUNT: NOT MOUNT  SIZECODESMD: 1608  (hidden comment: C)
C933  VAL1: 4.7nF(J)  VAL2: 50V  SIZECODESMD: 1608  (hidden comment: C)
C934  VAL1: 4.7nF(J)  VAL2: 50V  SIZECODESMD: 1608  (hidden comment: C)
C935  VAL1: 4.7nF(J)  VAL2: 50V  SIZECODESMD: 1608  (hidden comment: C)
C936  VAL1: 0.1uF(K)  VAL2: 50V  SIZECODESMD: 1608  (hidden comment: C)
C937  VAL1: 0.1uF(K)  VAL2: 50V  SIZECODESMD: 1608  (hidden comment: C)
C938  VAL1: 0.1uF(K)  VAL2: 50V  SIZECODESMD: 1608  (hidden comment: C)
C939  VAL1: 0.1uF(K)  VAL2: 50V  SIZECODESMD: 1608  (hidden comment: C)
CN307  B2P-VH
CN308  B2P-VH
CN924  VAL3: TSM-102-01-L-SV  (hidden comment: C2A)
CN925  TP  (value not drawn)
CN926  VAL3: TSM-102-01-L-SV  (hidden comment: C2A)
CN927  VAL3: TSM-102-01-L-SV  (hidden comment: C2A)
CN928  TP  (value not drawn)
CN929  VAL3: TSM-102-01-L-SV  (hidden comment: C2A)
CN936  B2P-VH
CN937  VAL3: TSM-102-01-L-SV  (hidden comment: C2A)
CN938  TP  (value not drawn)
CN939  VAL3: TSM-102-01-L-SV  (hidden comment: C2A)
D731  USERCOMPTEXT3: TOSHIBA  VAL3: 1SS362FV  (hidden comment: DEW)
D732  USERCOMPTEXT3: TOSHIBA  VAL3: 1SS362FV  (hidden comment: DEW)
D813  USERCOMPTEXT3: TOSHIBA  VAL3: 1SS362FV  (hidden comment: DEW)
IC730  TLVH431AQDBVRQ1
IC731  TLVH431AQDBVRQ1
IC732  TLVH431AQDBVRQ1
IC733  INA290A2QDCKRQ1
IC734  INA290A2QDCKRQ1
IC735  TS5A3159QDBVRQ1
IC736  INA290A2QDCKRQ1
IC737  INA290A2QDCKRQ1
IC738  TS5A3159QDBVRQ1
IC739  TLVH431AQDBVRQ1
IC823  TLVH431AQDBVRQ1
IC824  TLVH431AQDBVRQ1
IC825  INA290A2QDCKRQ1
IC826  INA290A2QDCKRQ1
IC827  TS5A3159QDBVRQ1
IC828  TS5A3159QDBVRQ1
Q731  USERCOMPTEXT3: TOSHIBA  VAL3: 2SC4117-GR  (hidden comment: TRN)
Q732  USERCOMPTEXT1: 1/2  USERCOMPTEXT3: TOSHIBA  VAL3: RN4907  (hidden comment: RN4907_Q2)  (parts A,B of 2)
Q733  USERCOMPTEXT3: TOSHIBA  VAL3: 2SC4117-GR  (hidden comment: TRN)
Q734  USERCOMPTEXT1: 1/2  USERCOMPTEXT3: TOSHIBA  VAL3: RN4907  (hidden comment: RN4907_Q2)  (parts A,B of 2)
Q736  USERCOMPTEXT3: TOSHIBA  VAL3: 2SC4117-GR  (hidden comment: TRN)
Q737  USERCOMPTEXT1: 1/2  USERCOMPTEXT3: TOSHIBA  VAL3: RN4907  (hidden comment: RN4907_Q2)  (parts A,B of 2)
Q738  USERCOMPTEXT3: TOSHIBA  VAL3: 2SC4117-GR  (hidden comment: TRN)
Q739  USERCOMPTEXT1: 1/2  USERCOMPTEXT3: TOSHIBA  VAL3: RN4907  (hidden comment: RN4907_Q2)  (parts A,B of 2)
Q823  USERCOMPTEXT3: TOSHIBA  VAL3: 2SC4117-GR  (hidden comment: TRN)
Q824  USERCOMPTEXT1: 1/2  USERCOMPTEXT3: TOSHIBA  VAL3: RN4907  (hidden comment: RN4907_Q2)  (parts A,B of 2)
Q825  USERCOMPTEXT3: TOSHIBA  VAL3: 2SC4117-GR  (hidden comment: TRN)
Q826  USERCOMPTEXT1: 1/2  USERCOMPTEXT3: TOSHIBA  VAL3: RN4907  (hidden comment: RN4907_Q2)  (parts A,B of 2)
R703  VAL1: 0  SIZECODESMD: 1608  (hidden comment: R)
R708  VAL1: 47(F)  SIZECODESMD: 1608  (hidden comment: R)
R713  VAL1: 0  SIZECODESMD: 1608  (hidden comment: R)
R718  VAL1: 0  SIZECODESMD: 1608  (hidden comment: R)
R760  NOTMOUNT: NOT MOUNT  SIZECODESMD: 1608  (hidden comment: R)
R761  NOTMOUNT: NOT MOUNT  SIZECODESMD: 1608  (hidden comment: R)
R762  VAL1: 22k(F)  SIZECODESMD: 1608  (hidden comment: R)
R763  VAL1: 22k(F)  SIZECODESMD: 1608  (hidden comment: R)
R764  VAL1: 1k(F)  SIZECODESMD: 1608  (hidden comment: R)
R765  VAL1: 1k(F)  SIZECODESMD: 1608  (hidden comment: R)
R766  VAL1: 1k(F)  SIZECODESMD: 1608  (hidden comment: R)
R767  VAL1: 1k(F)  SIZECODESMD: 1608  (hidden comment: R)
R768  VAL1: 2.7k(F)  SIZECODESMD: 1608  (hidden comment: R)
R769  VAL1: 2.7k(F)  SIZECODESMD: 1608  (hidden comment: R)
R770  VAL1: 10(J)  SIZECODESMD: 3216  (hidden comment: R)
R771  VAL1: 10(J)  SIZECODESMD: 3216  (hidden comment: R)
R772  VAL1: 10(J)  SIZECODESMD: 3216  (hidden comment: R)
R773  VAL1: 10(J)  SIZECODESMD: 3216  (hidden comment: R)
R774  VAL1: 10k(J)  SIZECODESMD: 1608  (hidden comment: R)
R775  VAL1: 10k(J)  SIZECODESMD: 1608  (hidden comment: R)
R776  VAL1: 47(F)  SIZECODESMD: 1608  (hidden comment: R)
R777  VAL1: 47(F)  SIZECODESMD: 1608  (hidden comment: R)
R778  VAL1: 47(F)  SIZECODESMD: 1608  (hidden comment: R)
R779  NOTMOUNT: NOT MOUNT  SIZECODESMD: 1608  (hidden comment: R)
R860  NOTMOUNT: NOT MOUNT  SIZECODESMD: 1608  (hidden comment: R)
R861  NOTMOUNT: NOT MOUNT  SIZECODESMD: 1608  (hidden comment: R)
R862  VAL1: 22k(F)  SIZECODESMD: 1608  (hidden comment: R)
R863  VAL1: 22k(F)  SIZECODESMD: 1608  (hidden comment: R)
R864  VAL1: 1k(F)  SIZECODESMD: 1608  (hidden comment: R)
R865  VAL1: 1k(F)  SIZECODESMD: 1608  (hidden comment: R)
R866  VAL1: 1k(F)  SIZECODESMD: 1608  (hidden comment: R)
R867  VAL1: 1k(F)  SIZECODESMD: 1608  (hidden comment: R)
R868  VAL1: 2.7k(F)  SIZECODESMD: 1608  (hidden comment: R)
R869  VAL1: 2.7k(F)  SIZECODESMD: 1608  (hidden comment: R)
R870  VAL1: 10(J)  SIZECODESMD: 3216  (hidden comment: R)
R871  VAL1: 10(J)  SIZECODESMD: 3216  (hidden comment: R)
R872  VAL1: 10(J)  SIZECODESMD: 3216  (hidden comment: R)
R873  VAL1: 10(J)  SIZECODESMD: 3216  (hidden comment: R)
R874  VAL1: 10k(J)  SIZECODESMD: 1608  (hidden comment: R)
R875  VAL1: 10k(J)  SIZECODESMD: 1608  (hidden comment: R)
R876  VAL1: 47(F)  SIZECODESMD: 1608  (hidden comment: R)
R877  VAL1: 47(F)  SIZECODESMD: 1608  (hidden comment: R)
R878  VAL1: 47(F)  SIZECODESMD: 1608  (hidden comment: R)
R879  NOTMOUNT: NOT MOUNT  SIZECODESMD: 1608  (hidden comment: R)
R903  VAL1: 0  SIZECODESMD: 1608  (hidden comment: R)
R908  VAL1: 47(F)  SIZECODESMD: 1608  (hidden comment: R)
R913  VAL1: 0  SIZECODESMD: 1608  (hidden comment: R)
R918  VAL1: 0  SIZECODESMD: 1608  (hidden comment: R)
R960  NOTMOUNT: NOT MOUNT  SIZECODESMD: 1608  (hidden comment: R)
R961  NOTMOUNT: NOT MOUNT  SIZECODESMD: 1608  (hidden comment: R)
R962  VAL1: 22k(F)  SIZECODESMD: 1608  (hidden comment: R)
R963  VAL1: 22k(F)  SIZECODESMD: 1608  (hidden comment: R)
R964  VAL1: 1k(F)  SIZECODESMD: 1608  (hidden comment: R)
R965  VAL1: 1k(F)  SIZECODESMD: 1608  (hidden comment: R)
R966  VAL1: 1k(F)  SIZECODESMD: 1608  (hidden comment: R)
R967  VAL1: 1k(F)  SIZECODESMD: 1608  (hidden comment: R)
R968  VAL1: 2.7k(F)  SIZECODESMD: 1608  (hidden comment: R)
R969  VAL1: 2.7k(F)  SIZECODESMD: 1608  (hidden comment: R)
R970  VAL1: 10(J)  SIZECODESMD: 3216  (hidden comment: R)
R971  VAL1: 10(J)  SIZECODESMD: 3216  (hidden comment: R)
R972  VAL1: 10(J)  SIZECODESMD: 3216  (hidden comment: R)
R973  VAL1: 10(J)  SIZECODESMD: 3216  (hidden comment: R)
R974  VAL1: 10k(J)  SIZECODESMD: 1608  (hidden comment: R)
R975  VAL1: 10k(J)  SIZECODESMD: 1608  (hidden comment: R)
R976  VAL1: 47(F)  SIZECODESMD: 1608  (hidden comment: R)
R977  VAL1: 47(F)  SIZECODESMD: 1608  (hidden comment: R)
R979  NOTMOUNT: NOT MOUNT  SIZECODESMD: 1608  (hidden comment: R)
U?#11  DATE: 2025/02/21  DRAWINGNUMBER: RD210-SCHEMATIC2-01  TITLE: Automotive 3kW 48V-12V Bidirectional / DC-DC Converter  FUNCTION: Current Sensing Circuit(BLOCK 2)  SHEETNUMBER: 11/12  REVISION: 01  (hidden comment: WAKU_DEF_A3)

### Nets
GND-1: Q739.4
GND-3: C756.2 C757.2 C758.2 C766.2 C767.2 C768.2 C936.2 C937.2 C938.2 C939.2 CN925.1 CN928.1 CN938.1 D731.1(A) D732.1(A) D813.1(A) IC730.5 IC731.5 IC732.5 IC733.2 IC734.2 IC735.2 IC736.2 IC737.2 IC738.2 IC739.5 IC823.5 IC824.5 IC825.2 IC826.2 IC827.2 IC828.2 Q732.4 Q734.4 Q737.4 Q824.4 Q826.4 R768.1 R769.1 R774.2 R775.2 R868.1 R869.1 R874.2 R875.2 R968.1 R969.1 R974.2 R975.2
VDDA: D731.2(C) D732.2(C) D813.2(C)
VP_5R0-1234: C756.1 C757.1 C758.1 C766.1 C767.1 C768.1 C936.1 C937.1 C938.1 C939.1 IC733.3 IC734.3 IC735.5 IC736.3 IC737.3 IC738.5 IC825.3 IC826.3 IC827.5 IC828.5 Q732.1 Q734.1 Q737.1 Q739.1 Q824.1 Q826.1
BIAS_1_ON-3: Q734.5 Q737.5 Q824.5 ; off-sheet BIAS_1_ON-3
BIAS_2_ON-3: Q732.5 Q739.5 Q826.5 ; off-sheet BIAS_2_ON-3
I_C0-3: IC828.3 R977.2 ; off-sheet I_C0-3
I_H0-3: D813.3(AC) R908.2 ; off-sheet I_H0-3
I_H0_B-3: D731.3(AC) IC828.1 R777.2 ; off-sheet I_H0_B-3
I_L0-3: D732.3(AC) R877.2 ; off-sheet I_L0-3
I_SEL_3: R776.2 R876.2 R976.2 ; off-sheet I_SEL_3
I_SEL_CM-3: R708.2 ; off-sheet I_SEL_CM-3
SIG0111: CN927.1 IC736.1 R713.1 R874.1
SIG0112: C760.1 R860.2
SIG0113: IC731.4 R760.1 R766.2
SIG0114: Q738.1(B) R865.1
SIG0115: CN924.2 IC735.1 R703.2
SIG0116: CN929.1 IC737.1 R875.1 R913.1
SIG0117: C754.2 IC733.4 R771.2
SIG0118: Q824.2 Q824.3
SIG0119: C750.1 R760.2
SIG01110: IC739.4 R860.1 R866.2
SIG01111: Q736.1(B) R864.1
SIG01112: Q826.2 Q826.3
SIG01113: IC735.4 R777.1
SIG01114: CN929.2 IC738.1 R913.2
SIG01115: C762.1 C763.1 C889.1 CN308.1 R870.1 R872.1 R879.2
SIG01116: CN937.2 IC827.3 R718.2
SIG01117: CN924.1 IC733.1 R703.1 R774.1
SIG01118: IC828.6 R708.1
SIG01119: IC738.6 R876.1
SIG01120: Q731.1(B) R764.1
SIG01121: Q739.6 R863.2
SIG01122: IC730.4 R861.1 R867.2
SIG01123: IC735.6 R776.1
SIG01124: CN926.2 IC735.3 R903.2
SIG01125: CN927.2 IC738.3 R713.2
SIG01126: Q732.6 R762.2
SIG01127: IC828.4 R908.1
SIG01128: IC738.4 R877.1
SIG01129: IC732.4 R761.1 R767.2
SIG01130: C931.1 R961.2
SIG01131: CN939.1 IC826.1 R918.1 R975.1
SIG01132: Q739.2 Q739.3
SIG01133: C765.2 IC737.4 R872.2
SIG01134: C751.2 IC732.3 R763.1 R765.2
SIG01135: C843.1 IC734.5 Q733.3(C) R773.1
SIG01136: IC827.4 R977.1
SIG01137: C889.2 CN308.2 R878.1 R879.1
SIG01138: C930.1 R960.2
SIG01139: Q737.6 R862.2
SIG01140: Q733.1(B) R765.1
SIG01141: C931.2 IC824.3 R963.1 R965.2
SIG01142: C752.1 C753.1 C888.1 CN307.1 R770.1 R772.1 R779.2
SIG01143: C935.1 IC826.5 Q825.3(C) R973.1
SIG01144: IC823.4 R960.1 R966.2
SIG01145: C752.2 C753.2 R771.1 R773.2 R778.2
SIG01146: Q732.2 Q732.3
SIG01147: IC827.6 R976.1
SIG01148: C888.2 CN307.2 R778.1 R779.1
SIG01149: Q824.6 R962.2
SIG01150: C751.1 R761.2
SIG01151: Q826.6 R963.2
SIG01152: CN939.2 IC827.1 R918.2
SIG01153: Q823.1(B) R964.1
SIG01154: Q825.1(B) R965.1
SIG01155: Q734.2 Q734.3
SIG01156: C762.2 C763.2 R871.1 R873.2 R878.2
SIG01157: Q737.2 Q737.3
SIG01158: Q731.2(E) R766.1 R768.2
SIG01159: C935.2 IC826.4 R972.2
SIG01160: C764.1 IC736.5 Q736.3(C) R870.2
SIG01161: C750.2 IC731.3 R762.1 R764.2
SIG01162: Q734.6 R763.2
SIG01163: C934.2 IC825.4 R971.2
SIG01164: CN937.1 IC825.1 R718.1 R974.1
SIG01165: C760.2 IC739.3 R862.1 R864.2
SIG01166: Q733.2(E) R767.1 R769.2
SIG01167: Q738.2(E) R867.1 R869.2
SIG01168: IC824.4 R961.1 R967.2
SIG01169: Q736.2(E) R866.1 R868.2
SIG01170: C754.1 IC733.5 Q731.3(C) R770.2
SIG01171: C761.1 R861.2
SIG01172: C843.2 IC734.4 R772.2
SIG01173: C934.1 IC825.5 Q823.3(C) R970.2
SIG01174: C761.2 IC730.3 R863.1 R865.2
SIG01175: C933.1 CN936.1 R970.1 R972.1 R979.2
SIG01176: C930.2 IC823.3 R962.1 R964.2
SIG01177: Q825.2(E) R967.1 R969.2
SIG01178: C764.2 IC736.4 R871.2
SIG01179: CN926.1 IC734.1 R775.1 R903.1
SIG01180: C765.1 IC737.5 Q738.3(C) R873.1
SIG01181: Q823.2(E) R966.1 R968.2
SIG01182: C933.2 CN936.2 R971.1 R973.2 R979.1

Not connected (* = marked no-connect by the designer): IC730 1 2; IC731 1 2; IC732 1 2; IC739 1 2; IC823 1 2; IC824 1 2

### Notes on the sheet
- ※CN307 is connected to CN208 of RD210-SCHEMATIC1
- ※CN308 is connected to CN209 of RD210-SCHEMATIC1
- ※CN936 is connected to CN210 of RD210-SCHEMATIC1
- <Current Sensing Circuit>
- BLOCK 2:Hi-Voltage Side
- BLOCK 2:Low-Voltage Side
- BLOCK 2:Coil Current

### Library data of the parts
C750 C751 C760 C761 C930 C931 = C: as C730 on sheet 10
C752-C754 C756-C758 C762-C768 C843 C933-C939 = C: OriginalSymbolOrigin: (2540,7620)
C888 C889 = C: as C886 on sheet 10
CN307 CN308 CN936 = B2P-VH: as CN208 on sheet 10
CN924 CN926 CN927 CN929 CN937 CN939 = C2A: as CN511 on sheet 10
CN925 CN928 CN938 = TP: as CN512 on sheet 10
D731 D732 D813 = DEW: as D721 on sheet 10
IC730-IC732 IC739 IC823 IC824 = TLVH431AQDBVRQ1: as IC720-IC722 on sheet 10
IC733 IC734 IC736 IC737 IC825 IC826 = INA290A2QDCKRQ1: as IC723 on sheet 10
IC735 IC738 IC827 IC828 = TS5A3159QDBVRQ1: as IC725 on sheet 10
Q731 Q733 Q736 Q738 Q823 Q825 = TRN: as Q721 on sheet 10
Q732 Q734 Q737 Q739 Q824 Q826 = RN4907_Q2: as Q722 on sheet 10
R703 R713 R718 R903 R913 R918 = R: OriginalSymbolOrigin: (5080,5080)
R708 R764-R767 R776-R778 R864-R867 R876-R878 R908 R964-R967 R976 R977 = R: as R707 on sheet 10
R760 R761 R860 R861 R960 R961 = R: as R740 on sheet 10
R762 R763 R768 R769 R774 R775 R862 R863 R868 R869 R874 R875 R962 R963 R968 R969 R974 R975 = R: as R742 on sheet 10
R770-R773 R870-R873 R970-R973 = R: as R750-R753 on sheet 10
R779 R879 R979 = R: as R759 on sheet 10
U?#11 = WAKU_DEF_A3: PLOTTIME: HH:MM; SAVEAREA0: 96913,-567914,509243,-368858; TIME: 19:41:36; UPDATEUSER: t5459927; UPDATETIME: 06:59:19; SAVECOUNT: 20; ZONEOFFSETX: 36; ZONEOFFSETY: -24; OriginalSymbolOrigin: (12700,-12700); SHTSAVECOUNT: 16

## Sheet 12.SchDoc
size 609 x 444 mm
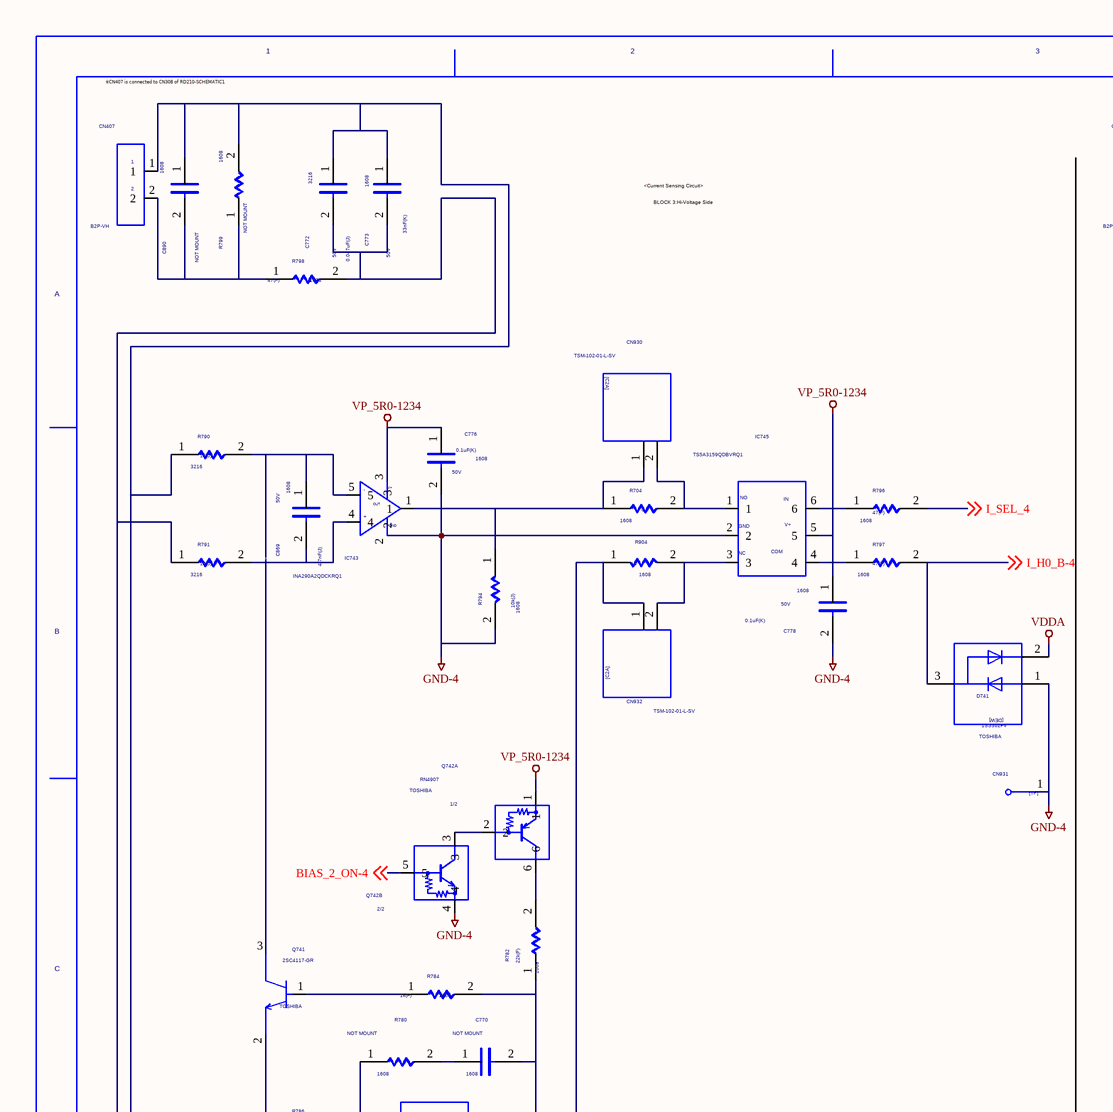
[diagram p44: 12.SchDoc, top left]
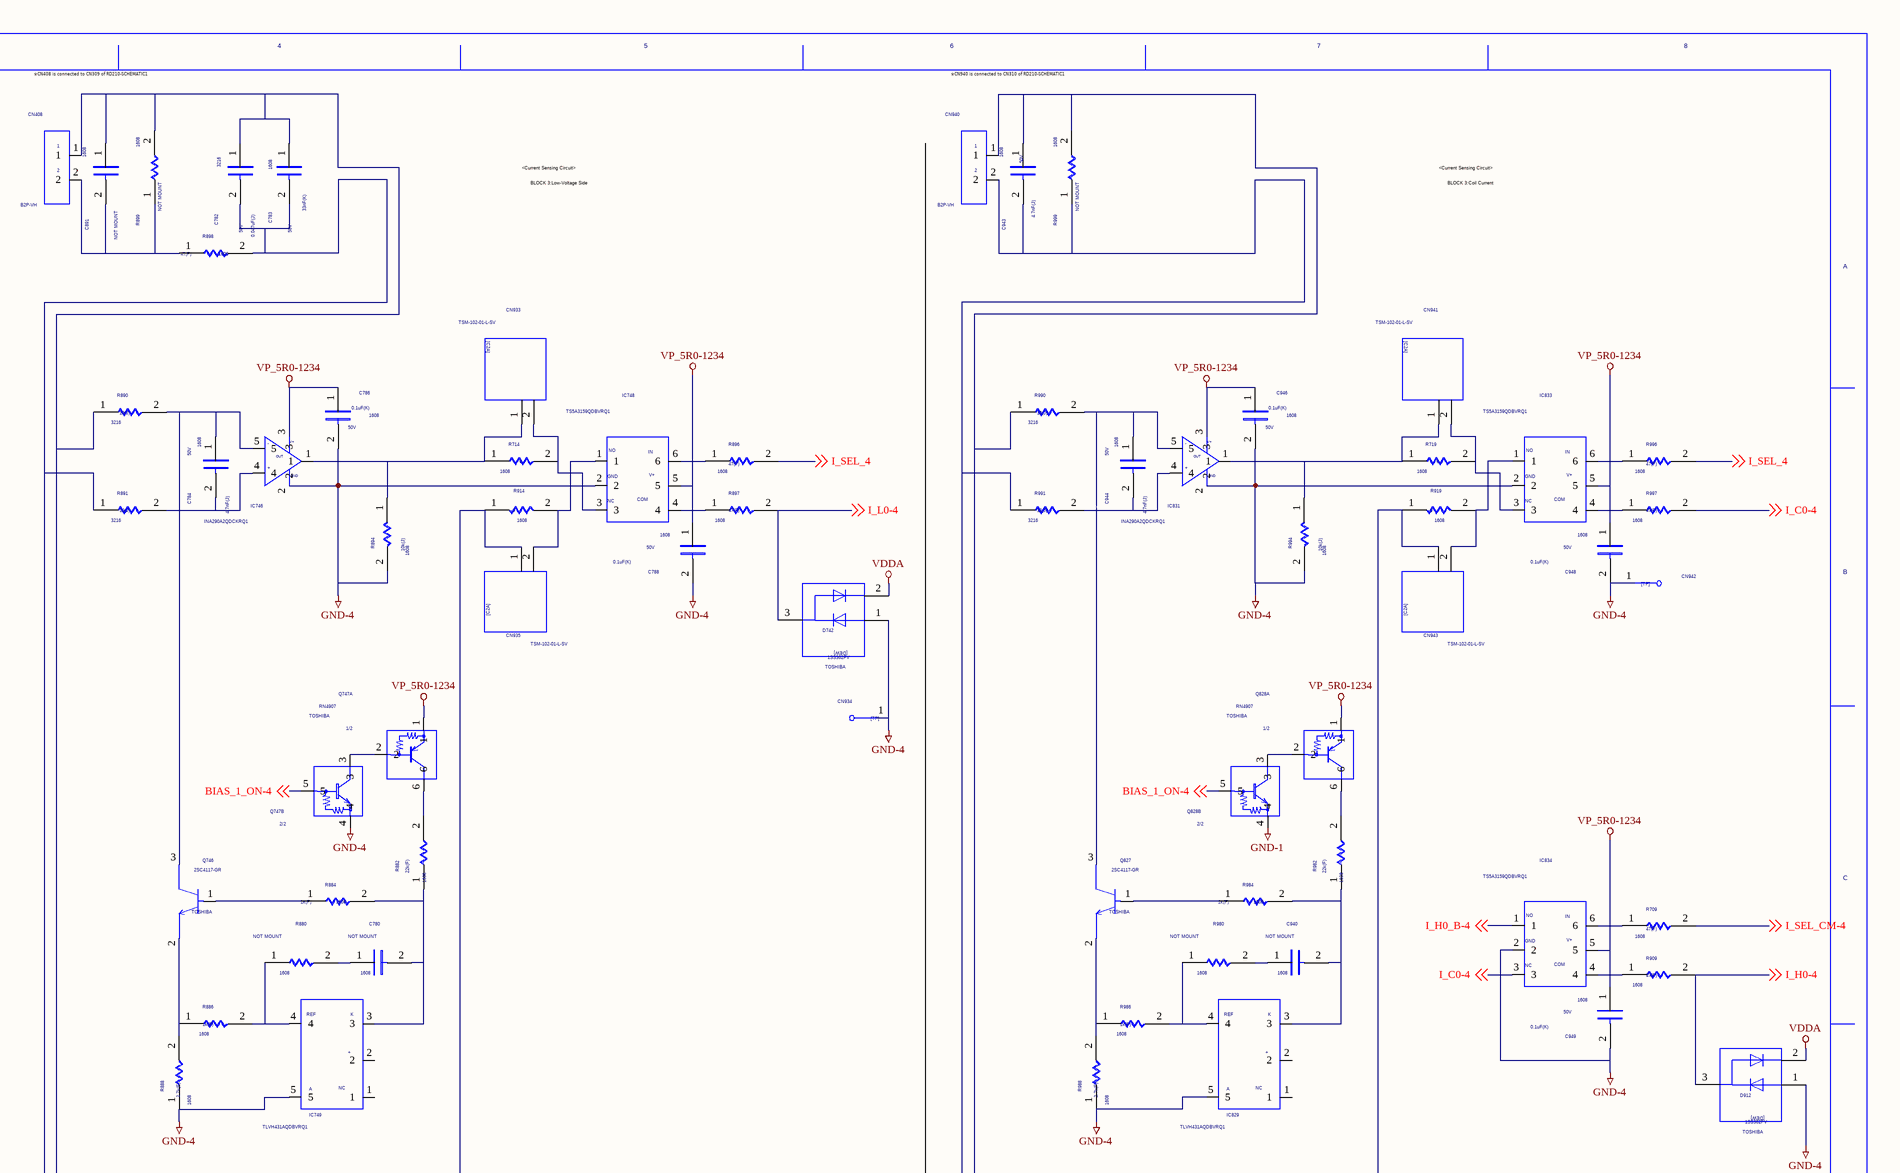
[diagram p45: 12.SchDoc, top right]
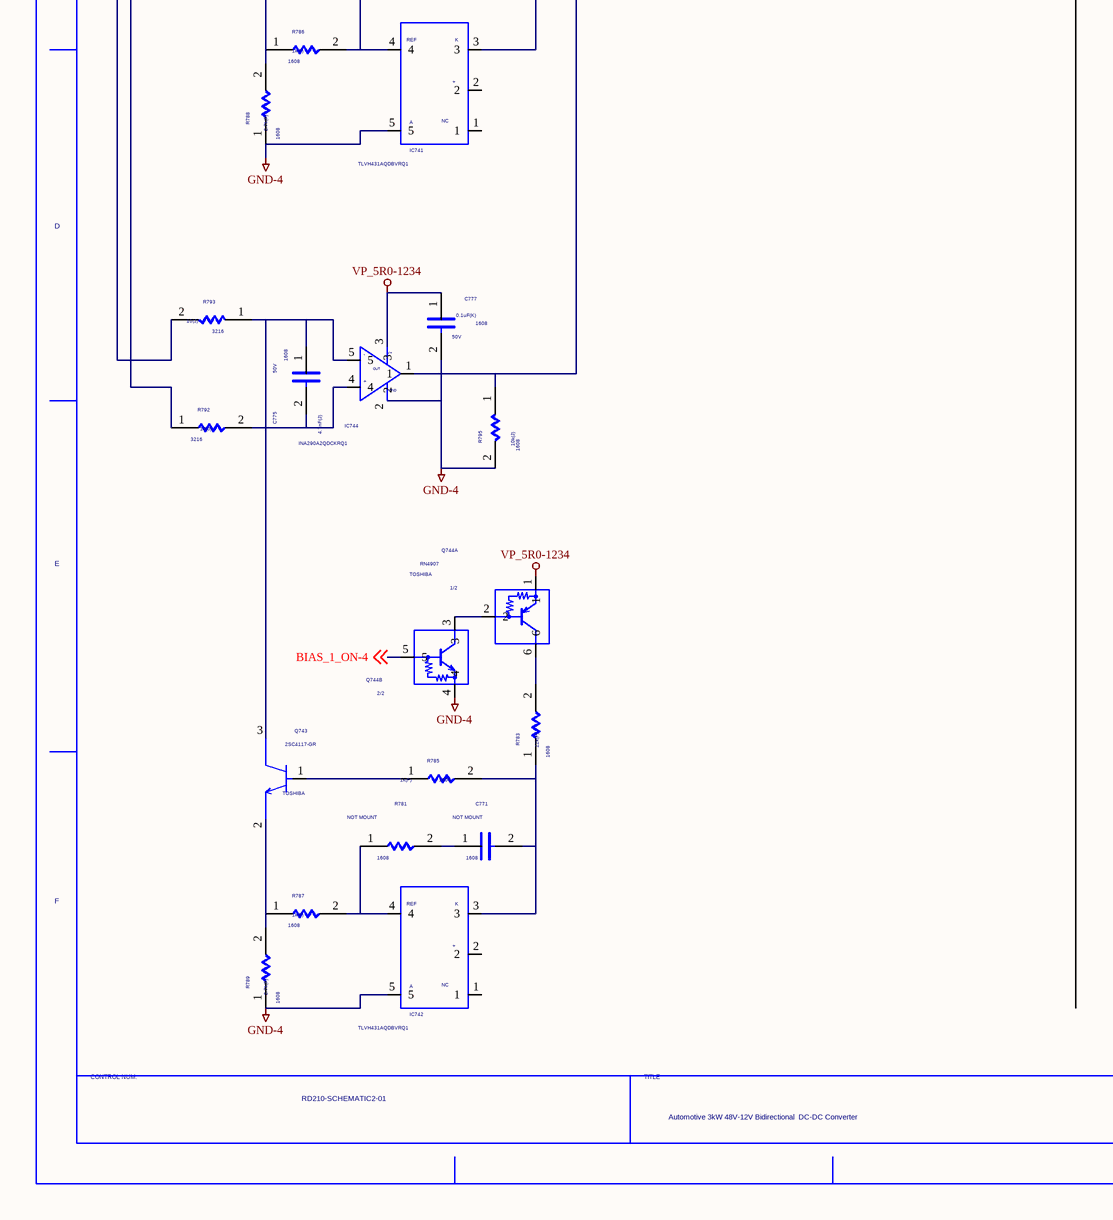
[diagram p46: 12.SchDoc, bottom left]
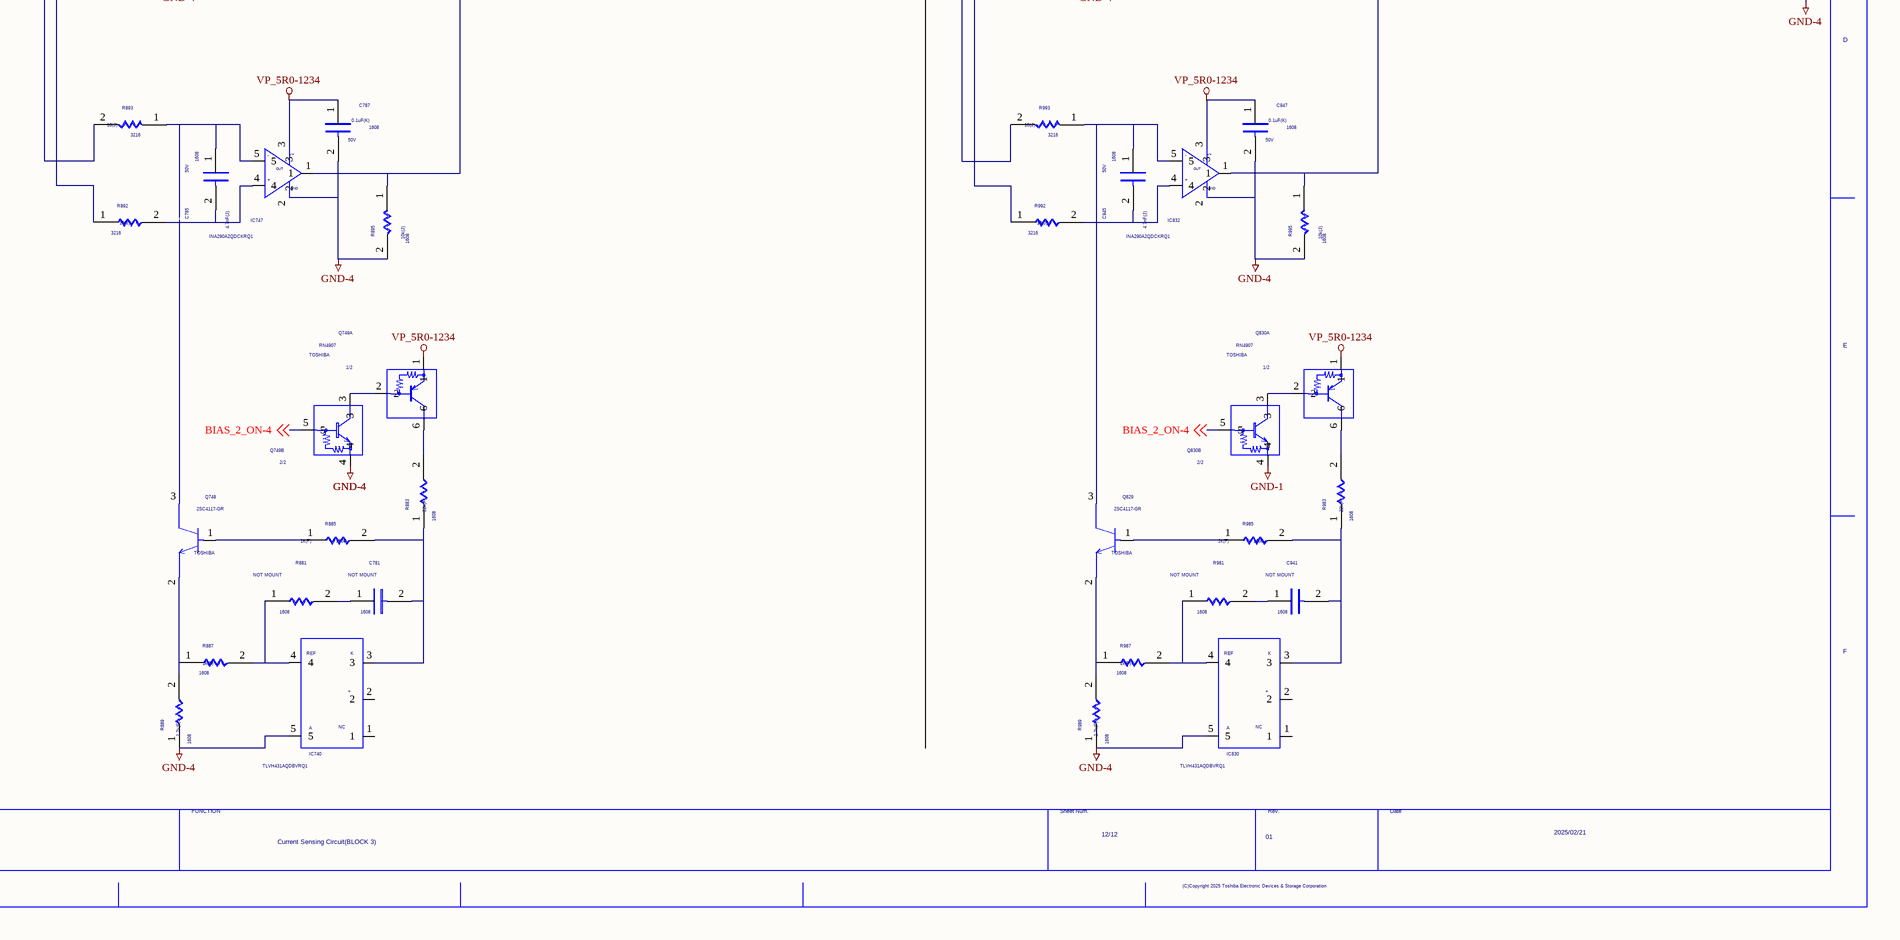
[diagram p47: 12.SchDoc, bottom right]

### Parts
(Parts that share a designator on the sheet are numbered #1, #2 ... from top to bottom, then left to right.)
C770  NOTMOUNT: NOT MOUNT  SIZECODESMD: 1608  (hidden comment: C)
C771  NOTMOUNT: NOT MOUNT  SIZECODESMD: 1608  (hidden comment: C)
C772  VAL1: 0.047uF(J)  VAL2: 50V  SIZECODESMD: 3216  (hidden comment: C)
C773  VAL1: 33nF(K)  VAL2: 50V  SIZECODESMD: 1608  (hidden comment: C)
C775  VAL1: 4.7nF(J)  VAL2: 50V  SIZECODESMD: 1608  (hidden comment: C)
C776  VAL1: 0.1uF(K)  VAL2: 50V  SIZECODESMD: 1608  (hidden comment: C)
C777  VAL1: 0.1uF(K)  VAL2: 50V  SIZECODESMD: 1608  (hidden comment: C)
C778  VAL1: 0.1uF(K)  VAL2: 50V  SIZECODESMD: 1608  (hidden comment: C)
C780  NOTMOUNT: NOT MOUNT  SIZECODESMD: 1608  (hidden comment: C)
C781  NOTMOUNT: NOT MOUNT  SIZECODESMD: 1608  (hidden comment: C)
C782  VAL1: 0.047uF(J)  VAL2: 50V  SIZECODESMD: 3216  (hidden comment: C)
C783  VAL1: 33nF(K)  VAL2: 50V  SIZECODESMD: 1608  (hidden comment: C)
C784  VAL1: 4.7nF(J)  VAL2: 50V  SIZECODESMD: 1608  (hidden comment: C)
C785  VAL1: 4.7nF(J)  VAL2: 50V  SIZECODESMD: 1608  (hidden comment: C)
C786  VAL1: 0.1uF(K)  VAL2: 50V  SIZECODESMD: 1608  (hidden comment: C)
C787  VAL1: 0.1uF(K)  VAL2: 50V  SIZECODESMD: 1608  (hidden comment: C)
C788  VAL1: 0.1uF(K)  VAL2: 50V  SIZECODESMD: 1608  (hidden comment: C)
C869  VAL1: 4.7nF(J)  VAL2: 50V  SIZECODESMD: 1608  (hidden comment: C)
C890  NOTMOUNT: NOT MOUNT  SIZECODESMD: 1608  (hidden comment: C)
C891  NOTMOUNT: NOT MOUNT  SIZECODESMD: 1608  (hidden comment: C)
C940  NOTMOUNT: NOT MOUNT  SIZECODESMD: 1608  (hidden comment: C)
C941  NOTMOUNT: NOT MOUNT  SIZECODESMD: 1608  (hidden comment: C)
C943  VAL1: 4.7nF(J)  VAL2: 50V  SIZECODESMD: 1608  (hidden comment: C)
C944  VAL1: 4.7nF(J)  VAL2: 50V  SIZECODESMD: 1608  (hidden comment: C)
C945  VAL1: 4.7nF(J)  VAL2: 50V  SIZECODESMD: 1608  (hidden comment: C)
C946  VAL1: 0.1uF(K)  VAL2: 50V  SIZECODESMD: 1608  (hidden comment: C)
C947  VAL1: 0.1uF(K)  VAL2: 50V  SIZECODESMD: 1608  (hidden comment: C)
C948  VAL1: 0.1uF(K)  VAL2: 50V  SIZECODESMD: 1608  (hidden comment: C)
C949  VAL1: 0.1uF(K)  VAL2: 50V  SIZECODESMD: 1608  (hidden comment: C)
CN407  B2P-VH
CN408  B2P-VH
CN930  VAL3: TSM-102-01-L-SV  (hidden comment: C2A)
CN931  TP  (value not drawn)
CN932  VAL3: TSM-102-01-L-SV  (hidden comment: C2A)
CN933  VAL3: TSM-102-01-L-SV  (hidden comment: C2A)
CN934  TP  (value not drawn)
CN935  VAL3: TSM-102-01-L-SV  (hidden comment: C2A)
CN940  B2P-VH
CN941  VAL3: TSM-102-01-L-SV  (hidden comment: C2A)
CN942  TP  (value not drawn)
CN943  VAL3: TSM-102-01-L-SV  (hidden comment: C2A)
D741  USERCOMPTEXT3: TOSHIBA  VAL3: 1SS362FV  (hidden comment: DEW)
D742  USERCOMPTEXT3: TOSHIBA  VAL3: 1SS362FV  (hidden comment: DEW)
D912  USERCOMPTEXT3: TOSHIBA  VAL3: 1SS362FV  (hidden comment: DEW)
IC740  TLVH431AQDBVRQ1
IC741  TLVH431AQDBVRQ1
IC742  TLVH431AQDBVRQ1
IC743  INA290A2QDCKRQ1
IC744  INA290A2QDCKRQ1
IC745  TS5A3159QDBVRQ1
IC746  INA290A2QDCKRQ1
IC747  INA290A2QDCKRQ1
IC748  TS5A3159QDBVRQ1
IC749  TLVH431AQDBVRQ1
IC829  TLVH431AQDBVRQ1
IC830  TLVH431AQDBVRQ1
IC831  INA290A2QDCKRQ1
IC832  INA290A2QDCKRQ1
IC833  TS5A3159QDBVRQ1
IC834  TS5A3159QDBVRQ1
Q741  USERCOMPTEXT3: TOSHIBA  VAL3: 2SC4117-GR  (hidden comment: TRN)
Q742  USERCOMPTEXT1: 1/2  USERCOMPTEXT3: TOSHIBA  VAL3: RN4907  (hidden comment: RN4907_Q2)  (parts A,B of 2)
Q743  USERCOMPTEXT3: TOSHIBA  VAL3: 2SC4117-GR  (hidden comment: TRN)
Q744  USERCOMPTEXT1: 1/2  USERCOMPTEXT3: TOSHIBA  VAL3: RN4907  (hidden comment: RN4907_Q2)  (parts A,B of 2)
Q746  USERCOMPTEXT3: TOSHIBA  VAL3: 2SC4117-GR  (hidden comment: TRN)
Q747  USERCOMPTEXT1: 1/2  USERCOMPTEXT3: TOSHIBA  VAL3: RN4907  (hidden comment: RN4907_Q2)  (parts A,B of 2)
Q748  USERCOMPTEXT3: TOSHIBA  VAL3: 2SC4117-GR  (hidden comment: TRN)
Q749  USERCOMPTEXT1: 1/2  USERCOMPTEXT3: TOSHIBA  VAL3: RN4907  (hidden comment: RN4907_Q2)  (parts A,B of 2)
Q827  USERCOMPTEXT3: TOSHIBA  VAL3: 2SC4117-GR  (hidden comment: TRN)
Q828  USERCOMPTEXT1: 1/2  USERCOMPTEXT3: TOSHIBA  VAL3: RN4907  (hidden comment: RN4907_Q2)  (parts A,B of 2)
Q829  USERCOMPTEXT3: TOSHIBA  VAL3: 2SC4117-GR  (hidden comment: TRN)
Q830  USERCOMPTEXT1: 1/2  USERCOMPTEXT3: TOSHIBA  VAL3: RN4907  (hidden comment: RN4907_Q2)  (parts A,B of 2)
R704  VAL1: 0  SIZECODESMD: 1608  (hidden comment: R)
R709  VAL1: 47(F)  SIZECODESMD: 1608  (hidden comment: R)
R714  VAL1: 0  SIZECODESMD: 1608  (hidden comment: R)
R719  VAL1: 0  SIZECODESMD: 1608  (hidden comment: R)
R780  NOTMOUNT: NOT MOUNT  SIZECODESMD: 1608  (hidden comment: R)
R781  NOTMOUNT: NOT MOUNT  SIZECODESMD: 1608  (hidden comment: R)
R782  VAL1: 22k(F)  SIZECODESMD: 1608  (hidden comment: R)
R783  VAL1: 22k(F)  SIZECODESMD: 1608  (hidden comment: R)
R784  VAL1: 1k(F)  SIZECODESMD: 1608  (hidden comment: R)
R785  VAL1: 1k(F)  SIZECODESMD: 1608  (hidden comment: R)
R786  VAL1: 1k(F)  SIZECODESMD: 1608  (hidden comment: R)
R787  VAL1: 1k(F)  SIZECODESMD: 1608  (hidden comment: R)
R788  VAL1: 2.7k(F)  SIZECODESMD: 1608  (hidden comment: R)
R789  VAL1: 2.7k(F)  SIZECODESMD: 1608  (hidden comment: R)
R790  VAL1: 10(J)  SIZECODESMD: 3216  (hidden comment: R)
R791  VAL1: 10(J)  SIZECODESMD: 3216  (hidden comment: R)
R792  VAL1: 10(J)  SIZECODESMD: 3216  (hidden comment: R)
R793  VAL1: 10(J)  SIZECODESMD: 3216  (hidden comment: R)
R794  VAL1: 10k(J)  SIZECODESMD: 1608  (hidden comment: R)
R795  VAL1: 10k(J)  SIZECODESMD: 1608  (hidden comment: R)
R796  VAL1: 47(F)  SIZECODESMD: 1608  (hidden comment: R)
R797  VAL1: 47(F)  SIZECODESMD: 1608  (hidden comment: R)
R798  VAL1: 47(F)  SIZECODESMD: 1608  (hidden comment: R)
R799  NOTMOUNT: NOT MOUNT  SIZECODESMD: 1608  (hidden comment: R)
R880  NOTMOUNT: NOT MOUNT  SIZECODESMD: 1608  (hidden comment: R)
R881  NOTMOUNT: NOT MOUNT  SIZECODESMD: 1608  (hidden comment: R)
R882  VAL1: 22k(F)  SIZECODESMD: 1608  (hidden comment: R)
R883  VAL1: 22k(F)  SIZECODESMD: 1608  (hidden comment: R)
R884  VAL1: 1k(F)  SIZECODESMD: 1608  (hidden comment: R)
R885  VAL1: 1k(F)  SIZECODESMD: 1608  (hidden comment: R)
R886  VAL1: 1k(F)  SIZECODESMD: 1608  (hidden comment: R)
R887  VAL1: 1k(F)  SIZECODESMD: 1608  (hidden comment: R)
R888  VAL1: 2.7k(F)  SIZECODESMD: 1608  (hidden comment: R)
R889  VAL1: 2.7k(F)  SIZECODESMD: 1608  (hidden comment: R)
R890  VAL1: 10(J)  SIZECODESMD: 3216  (hidden comment: R)
R891  VAL1: 10(J)  SIZECODESMD: 3216  (hidden comment: R)
R892  VAL1: 10(J)  SIZECODESMD: 3216  (hidden comment: R)
R893  VAL1: 10(J)  SIZECODESMD: 3216  (hidden comment: R)
R894  VAL1: 10k(J)  SIZECODESMD: 1608  (hidden comment: R)
R895  VAL1: 10k(J)  SIZECODESMD: 1608  (hidden comment: R)
R896  VAL1: 47(F)  SIZECODESMD: 1608  (hidden comment: R)
R897  VAL1: 47(F)  SIZECODESMD: 1608  (hidden comment: R)
R898  VAL1: 47(F)  SIZECODESMD: 1608  (hidden comment: R)
R899  NOTMOUNT: NOT MOUNT  SIZECODESMD: 1608  (hidden comment: R)
R904  VAL1: 0  SIZECODESMD: 1608  (hidden comment: R)
R909  VAL1: 47(F)  SIZECODESMD: 1608  (hidden comment: R)
R914  VAL1: 0  SIZECODESMD: 1608  (hidden comment: R)
R919  VAL1: 0  SIZECODESMD: 1608  (hidden comment: R)
R980  NOTMOUNT: NOT MOUNT  SIZECODESMD: 1608  (hidden comment: R)
R981  NOTMOUNT: NOT MOUNT  SIZECODESMD: 1608  (hidden comment: R)
R982  VAL1: 22k(F)  SIZECODESMD: 1608  (hidden comment: R)
R983  VAL1: 22k(F)  SIZECODESMD: 1608  (hidden comment: R)
R984  VAL1: 1k(F)  SIZECODESMD: 1608  (hidden comment: R)
R985  VAL1: 1k(F)  SIZECODESMD: 1608  (hidden comment: R)
R986  VAL1: 1k(F)  SIZECODESMD: 1608  (hidden comment: R)
R987  VAL1: 1k(F)  SIZECODESMD: 1608  (hidden comment: R)
R988  VAL1: 2.7k(F)  SIZECODESMD: 1608  (hidden comment: R)
R989  VAL1: 2.7k(F)  SIZECODESMD: 1608  (hidden comment: R)
R990  VAL1: 10(J)  SIZECODESMD: 3216  (hidden comment: R)
R991  VAL1: 10(J)  SIZECODESMD: 3216  (hidden comment: R)
R992  VAL1: 10(J)  SIZECODESMD: 3216  (hidden comment: R)
R993  VAL1: 10(J)  SIZECODESMD: 3216  (hidden comment: R)
R994  VAL1: 10k(J)  SIZECODESMD: 1608  (hidden comment: R)
R995  VAL1: 10k(J)  SIZECODESMD: 1608  (hidden comment: R)
R996  VAL1: 47(F)  SIZECODESMD: 1608  (hidden comment: R)
R997  VAL1: 47(F)  SIZECODESMD: 1608  (hidden comment: R)
R999  NOTMOUNT: NOT MOUNT  SIZECODESMD: 1608  (hidden comment: R)
U?#12  DATE: 2025/02/21  DRAWINGNUMBER: RD210-SCHEMATIC2-01  TITLE: Automotive 3kW 48V-12V Bidirectional / DC-DC Converter  FUNCTION: Current Sensing Circuit(BLOCK 3)  SHEETNUMBER: 12/12  REVISION: 01  (hidden comment: WAKU_DEF_A3)

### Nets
GND-1: Q828.4 Q830.4
GND-4: C776.2 C777.2 C778.2 C786.2 C787.2 C788.2 C946.2 C947.2 C948.2 C949.2 CN931.1 CN934.1 CN942.1 D741.1(A) D742.1(A) D912.1(A) IC740.5 IC741.5 IC742.5 IC743.2 IC744.2 IC745.2 IC746.2 IC747.2 IC748.2 IC749.5 IC829.5 IC830.5 IC831.2 IC832.2 IC833.2 IC834.2 Q742.4 Q744.4 Q747.4 Q749.4 R788.1 R789.1 R794.2 R795.2 R888.1 R889.1 R894.2 R895.2 R988.1 R989.1 R994.2 R995.2
VDDA: D741.2(C) D742.2(C) D912.2(C)
VP_5R0-1234: C776.1 C777.1 C778.1 C786.1 C787.1 C788.1 C946.1 C947.1 C948.1 C949.1 IC743.3 IC744.3 IC745.5 IC746.3 IC747.3 IC748.5 IC831.3 IC832.3 IC833.5 IC834.5 Q742.1 Q744.1 Q747.1 Q749.1 Q828.1 Q830.1
BIAS_1_ON-4: Q744.5 Q747.5 Q828.5 ; off-sheet BIAS_1_ON-4
BIAS_2_ON-4: Q742.5 Q749.5 Q830.5 ; off-sheet BIAS_2_ON-4
I_C0-4: IC834.3 R997.2 ; off-sheet I_C0-4
I_H0-4: D912.3(AC) R909.2 ; off-sheet I_H0-4
I_H0_B-4: D741.3(AC) IC834.1 R797.2 ; off-sheet I_H0_B-4
I_L0-4: D742.3(AC) R897.2 ; off-sheet I_L0-4
I_SEL_4: R796.2 R896.2 R996.2 ; off-sheet I_SEL_4
I_SEL_CM-4: R709.2 ; off-sheet I_SEL_CM-4
SIG0121: Q830.2 Q830.3
SIG0122: Q742.6 R782.2
SIG0123: IC749.4 R880.1 R886.2
SIG0124: C775.1 IC744.5 Q743.3(C) R793.1
SIG0125: Q746.1(B) R884.1
SIG0126: C941.2 IC830.3 R983.1 R985.2
SIG0127: Q827.2(E) R986.1 R988.2
SIG0128: IC833.4 R997.1
SIG0129: C945.2 IC832.4 R992.2
SIG01210: IC742.4 R781.1 R787.2
SIG01211: C770.2 IC741.3 R782.1 R784.2
SIG01212: Q747.6 R882.2
SIG01213: Q744.2 Q744.3
SIG01214: C941.1 R981.2
SIG01215: Q743.1(B) R785.1
SIG01216: C940.1 R980.2
SIG01217: C770.1 R780.2
SIG01218: Q743.2(E) R787.1 R789.2
SIG01219: CN935.1 IC747.1 R895.1 R914.1
SIG01220: C943.1 CN940.1 R990.1 R992.1 R999.2
SIG01221: CN943.1 IC832.1 R919.1 R995.1
SIG01222: Q828.2 Q828.3
SIG01223: Q748.1(B) R885.1
SIG01224: C781.2 IC740.3 R883.1 R885.2
SIG01225: C891.2 CN408.2 R898.1 R899.1
SIG01226: CN930.2 IC745.1 R704.2
SIG01227: IC748.4 R897.1
SIG01228: Q829.2(E) R987.1 R989.2
SIG01229: C940.2 IC829.3 R982.1 R984.2
SIG01230: C944.1 IC831.5 Q827.3(C) R990.2
SIG01231: C771.2 IC742.3 R783.1 R785.2
SIG01232: C775.2 IC744.4 R792.2
SIG01233: CN930.1 IC743.1 R704.1 R794.1
SIG01234: C869.1 IC743.5 Q741.3(C) R790.2
SIG01235: C945.1 IC832.5 Q829.3(C) R993.1
SIG01236: C785.1 IC747.5 Q748.3(C) R893.1
SIG01237: Q830.6 R983.2
SIG01238: IC834.6 R709.1
SIG01239: C890.2 CN407.2 R798.1 R799.1
SIG01240: CN932.1 IC744.1 R795.1 R904.1
SIG01241: C772.1 C773.1 C890.1 CN407.1 R790.1 R792.1 R799.2
SIG01242: IC745.6 R796.1
SIG01243: IC829.4 R980.1 R986.2
SIG01244: IC740.4 R881.1 R887.2
SIG01245: Q746.2(E) R886.1 R888.2
SIG01246: C781.1 R881.2
SIG01247: C771.1 R781.2
SIG01248: CN932.2 IC745.3 R904.2
SIG01249: Q741.1(B) R784.1
SIG01250: CN935.2 IC748.1 R914.2
SIG01251: IC833.6 R996.1
SIG01252: Q749.6 R883.2
SIG01253: C782.1 C783.1 C891.1 CN408.1 R890.1 R892.1 R899.2
SIG01254: IC830.4 R981.1 R987.2
SIG01255: C784.2 IC746.4 R891.2
SIG01256: Q742.2 Q742.3
SIG01257: Q748.2(E) R887.1 R889.2
SIG01258: IC748.6 R896.1
SIG01259: C772.2 C773.2 R791.1 R793.2 R798.2
SIG01260: CN941.2 IC833.3 R719.2
SIG01261: CN933.1 IC746.1 R714.1 R894.1
SIG01262: C944.2 IC831.4 R991.2
SIG01263: C784.1 IC746.5 Q746.3(C) R890.2
SIG01264: Q741.2(E) R786.1 R788.2
SIG01265: Q747.2 Q747.3
SIG01266: Q828.6 R982.2
SIG01267: C943.2 CN940.2 R991.1 R993.2 R999.1
SIG01268: C782.2 C783.2 R891.1 R893.2 R898.2
SIG01269: Q749.2 Q749.3
SIG01270: Q827.1(B) R984.1
SIG01271: IC741.4 R780.1 R786.2
SIG01272: C780.2 IC749.3 R882.1 R884.2
SIG01273: C780.1 R880.2
SIG01274: Q829.1(B) R985.1
SIG01275: CN933.2 IC748.3 R714.2
SIG01276: C869.2 IC743.4 R791.2
SIG01277: CN943.2 IC833.1 R919.2
SIG01278: IC745.4 R797.1
SIG01279: IC834.4 R909.1
SIG01280: C785.2 IC747.4 R892.2
SIG01281: CN941.1 IC831.1 R719.1 R994.1
SIG01282: Q744.6 R783.2

Not connected (* = marked no-connect by the designer): IC740 1 2; IC741 1 2; IC742 1 2; IC749 1 2; IC829 1 2; IC830 1 2

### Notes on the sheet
- ※CN407 is connected to CN308 of RD210-SCHEMATIC1
- ※CN408 is connected to CN309 of RD210-SCHEMATIC1
- ※CN940 is connected to CN310 of RD210-SCHEMATIC1
- <Current Sensing Circuit>
- BLOCK 3:Hi-Voltage Side
- BLOCK 3:Low-Voltage Side
- BLOCK 3:Coil Current

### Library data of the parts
C770 C771 C780 C781 C940 C941 = C: as C730 on sheet 10
C772 C773 C775-C778 C782-C788 C869 C943-C949 = C: OriginalSymbolOrigin: (2540,7620)
C890 C891 = C: as C886 on sheet 10
CN407 CN408 CN940 = B2P-VH: as CN208 on sheet 10
CN930 CN932 CN933 CN935 CN941 CN943 = C2A: as CN511 on sheet 10
CN931 CN934 CN942 = TP: as CN512 on sheet 10
D741 D742 D912 = DEW: as D721 on sheet 10
IC740-IC742 IC749 IC829 IC830 = TLVH431AQDBVRQ1: as IC720-IC722 on sheet 10
IC743 IC744 IC746 IC747 IC831 IC832 = INA290A2QDCKRQ1: as IC723 on sheet 10
IC745 IC748 IC833 IC834 = TS5A3159QDBVRQ1: as IC725 on sheet 10
Q741 Q743 Q746 Q748 Q827 Q829 = TRN: as Q721 on sheet 10
Q742 Q744 Q749 Q828 Q830 = RN4907_Q2: 7TH PART FIELD: RES.,; 4TH PART FIELD: VISHAY,; 3RD PART FIELD: CHIP; 2ND PART FIELD: 1-5%; 5TH PART FIELD: CRCW0805---RT6; 1ST PART FIELD: 1/8W; PARTS: 1; VAL1: VALUE; TIME: 08:44:45; UPDATEUSER: t4887876; UPDATETIME: 19:03:09; SAVECOUNT: 13; CLASS: DISCRETE; HETERO: RN4905_1,RN4905_2; FUNCTION: PNP&NPN_PCT; LEVEL: STD; PKG_TYPE: 2-2J1A; DEVICE: RN4905; SAVEAREA0: -13854,-30480,41847,0; DEVICENAME: DTC144EETL; OriginalSymbolOrigin: (0,12700); CaptureCellPackProp: RN4907_Q2A; COMPONENTNAME: R4907_1
Q747 = RN4907_Q2: as Q722 on sheet 10
R704 R714 R719 R904 R914 R919 = R: OriginalSymbolOrigin: (5080,5080)
R709 R784-R787 R796-R798 R884-R887 R896-R898 R909 R984-R987 R996 R997 = R: as R707 on sheet 10
R780 R781 R880 R881 R980 R981 = R: as R740 on sheet 10
R782 R783 R788 R789 R794 R795 R882 R883 R888 R889 R894 R895 R982 R983 R988 R989 R994 R995 = R: as R742 on sheet 10
R790-R793 R890-R893 R990-R993 = R: as R750-R753 on sheet 10
R799 R899 R999 = R: as R759 on sheet 10
U?#12 = WAKU_DEF_A3: PLOTTIME: HH:MM; SAVEAREA0: 96913,-567914,509243,-368858; TIME: 19:44:08; UPDATEUSER: t5459927; UPDATETIME: 14:01:10; SAVECOUNT: 20; ZONEOFFSETX: 36; ZONEOFFSETY: -24; OriginalSymbolOrigin: (12700,-12700); SHTSAVECOUNT: 14

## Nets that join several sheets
AGND: 1 (40 pins), 6 (6 pins)
DGND: 1 (19 pins), 2 (30 pins), 3 (30 pins), 4 (22 pins), 6 (19 pins)
GND: 1 (5 pins), 2 (5 pins), 3 (10 pins), 4 (19 pins), 5 (16 pins), 6 (7 pins), 8 (24 pins)
GND-1: 9 (50 pins), 11 (Q739.4), 12 (Q828.4 Q830.4)
GND_P0: 5 (5 pins), 7 (5 pins), 8 (15 pins)
GND_P1: 5 (CN101.6), 7 (C822.2 C826.1 C830.1 IC804.2)
GND_P2: 5 (CN201.6), 7 (C823.2 C827.1 C831.1 IC805.2)
GND_P3: 5 (CN301.6), 7 (C824.2 C828.1 C832.1 IC806.2)
VDD: 1 (C665.2 C666.2 IC600.16 IC600.21), 2 (C667.1 C668.1 IC600.61 IC600.76), 3 (7 pins), 4 (6 pins), 6 (J804.2)
VDDA: 1 (C676.2 C678.1 IC600.36 IC600.54), 5 (CN4.5 CN104.5 CN204.5 CN304.5), 6 (C660.2 C663.1 J827.1 L654.2), 9 (D711.2 D712.2 D713.2), 10 (D721.2 D722.2 D812.2), 11 (D731.2 D732.2 D813.2), 12 (D741.2 D742.2 D912.2)
VDDIO: 1 (10 pins), 2 (19 pins), 3 (19 pins), 4 (9 pins), 5 (CN1.1 CN101.1 CN201.1 CN301.1), 6 (C658.2 C661.2 C664.1 L652.2)
VDDOSC: 3 (C677.1 C679.1 IC600.120 IC600.125), 6 (C659.2 C662.1 L653.2)
VP_3R3V_SYS: 1 (R514.1 R515.1 R565.2 R569.2), 2 (7 pins), 3 (7 pins), 6 (7 pins)
VP_5R0: 2 (8 pins), 3 (8 pins), 4 (8 pins), 5 (CN1.2 CN101.2 CN201.2 CN301.2), 6 (J803.2 J826.1)
VP_5R0-1234: 6 (7 pins), 9 (26 pins), 10 (26 pins), 11 (26 pins), 12 (26 pins)
VP_5V_I0_0: 5 (CN1.4), 7 (L810.2)
VP_5V_I0_1: 5 (CN3.2), 7 (L811.2)
VP_5V_I0_2: 5 (CN4.2), 7 (L812.2)
VP_5V_I1_0: 5 (CN101.4), 7 (L813.2)
VP_5V_I1_1: 5 (CN103.2), 7 (L814.2)
VP_5V_I1_2: 5 (CN104.2), 7 (L815.2)
VP_5V_I2_0: 5 (CN201.4), 7 (L816.2)
VP_5V_I2_1: 5 (CN203.2), 7 (L817.2)
VP_5V_I2_2: 5 (CN204.2), 7 (L818.2)
VP_5V_I3_0: 5 (CN301.4), 7 (L819.2)
VP_5V_I3_1: 5 (CN303.2), 7 (L820.2)
VP_5V_I3_2: 5 (CN304.2), 7 (L821.2)
VP_12R0_SYS_I0_0: 5 (CN1.5), 7 (C821.1 C825.2 IC803.1 L802.2)
VP_12R0_SYS_I0_1: 5 (CN3.7), 7 (L806.2)
VP_12R0_SYS_I1_0: 5 (CN101.5), 7 (C822.1 C826.2 IC804.1 L803.2)
VP_12R0_SYS_I1_1: 5 (CN103.7), 7 (L807.2)
VP_12R0_SYS_I2_0: 5 (CN201.5), 7 (C823.1 C827.2 IC805.1 L804.2)
VP_12R0_SYS_I2_1: 5 (CN203.7), 7 (L808.2)
VP_12R0_SYS_I3_0: 5 (CN301.5), 7 (C824.1 C828.2 IC806.1 L805.2)
VP_12R0_SYS_I3_1: 5 (CN303.7), 7 (L809.2)
VREF_A: 1 (IC600.37 R562.1 R572.1 R665.2), 6 (IC601.1 IC601.2)
VREF_B: 1 (IC600.53 R664.1), 6 (IC601.6 IC601.7)
VREF_C: 1 (IC600.35 R592.1 R663.2), 6 (IC601.8 IC601.9)
VREF_D: 1 (IC600.55 R582.1 R662.1), 6 (IC601.13 IC601.14)
BIAS_1_ON-1: 1 (IC600.23), 9 (Q714.5 Q717.5 Q816.5)
BIAS_1_ON-2: 3 (IC600.134), 10 (Q724.5 Q727.5 Q820.5)
BIAS_1_ON-3: 2 (IC600.100), 11 (Q734.5 Q737.5 Q824.5)
BIAS_1_ON-4: 2 (IC600.86), 12 (Q744.5 Q747.5 Q828.5)
BIAS_2_ON-1: 1 (IC600.24), 9 (Q712.5 Q719.5 Q818.5)
BIAS_2_ON-2: 3 (IC600.136), 10 (Q722.5 Q729.5 Q822.5)
BIAS_2_ON-3: 2 (IC600.101), 11 (Q732.5 Q739.5 Q826.5)
BIAS_2_ON-4: 2 (IC600.87), 12 (Q742.5 Q749.5 Q830.5)
DIAG0-1: 1 (IC600.27 R515.2), 5 (CN3.6)
DIAG0-2: 3 (IC600.130 R525.1), 5 (CN103.6)
DIAG0-3: 2 (IC600.103 R535.1), 5 (CN203.6)
DIAG0-4: 3 (IC600.141 R545.2), 5 (CN303.6)
EN_1R2V: 3 (D620.2 IC620.1 R632.1), 6 (J829.2)
H_EN_0-1: 1 (IC600.8), 5 (CN4.3)
H_EN_0-2: 2 (IC600.67), 5 (CN104.3)
H_EN_0-3: 2 (IC600.90), 5 (CN204.3)
H_EN_0-4: 2 (IC600.110), 3 (IC600.110), 5 (CN304.3)
I_H0-1: 1 (R510.2), 9 (D713.3 R906.2)
I_H0-2: 1 (R520.2), 10 (D812.3 R907.2)
I_H0-3: 1 (R530.2), 11 (D813.3 R908.2)
I_H0-4: 1 (R540.2), 12 (D912.3 R909.2)
I_L0-1: 1 (R511.1), 9 (D712.3 R837.2)
I_L0-2: 1 (R521.1), 10 (D722.3 R857.2)
I_L0-3: 1 (R531.1), 11 (D732.3 R877.2)
I_L0-4: 1 (R541.1), 12 (D742.3 R897.2)
I_SEL_1: 4 (IC106.4), 9 (R736.2 R836.2 R936.2)
I_SEL_2: 4 (IC807.4), 10 (R756.2 R856.2 R956.2)
I_SEL_3: 4 (IC808.4), 11 (R776.2 R876.2 R976.2)
I_SEL_4: 4 (IC809.4), 12 (R796.2 R896.2 R996.2)
I_SEL_CM-1: 1 (IC600.14 R506.2), 9 (R706.2)
I_SEL_CM-2: 2 (IC600.71 R614.1), 10 (R707.2)
I_SEL_CM-3: 2 (IC600.95 R620.1), 11 (R708.2)
I_SEL_CM-4: 3 (IC600.111 R623.1), 12 (R709.2)
L_IN1_0-1: 1 (IC600.13), 5 (CN3.4)
L_IN1_0-2: 2 (IC600.83), 5 (CN103.4)
L_IN1_0-3: 2 (IC600.96), 5 (CN203.4)
L_IN1_0-4: 3 (IC600.133), 5 (CN303.4)
MES_EN_0-1: 1 (IC600.10), 5 (CN2.8)
MES_EN_0-2: 2 (IC600.70), 5 (CN102.8)
MES_EN_0-3: 2 (IC600.94), 5 (CN202.8)
MES_EN_0-4: 3 (IC600.112), 5 (CN302.8)
PowrGood_0-1: 1 (IC600.25 R514.2), 5 (CN4.1)
PowrGood_0-2: 2 (IC600.89 R524.1), 5 (CN104.1)
PowrGood_0-3: 2 (IC600.102 R534.1), 5 (CN204.1)
PowrGood_0-4: 3 (IC600.140 R544.2), 5 (CN304.1)
PWM_H_0-1: 4 (IC600.160 R551.2), 5 (CN2.2)
PWM_H_0-2: 4 (IC600.164 R552.2), 5 (CN102.2)
PWM_H_0-3: 1 (IC600.1 R553.2), 5 (CN202.2)
PWM_H_0-4: 1 (IC600.4 R554.2), 5 (CN302.2)
PWM_L_0-1: 4 (IC600.161 R556.2), 5 (CN2.1)
PWM_L_0-2: 4 (IC600.165 R557.2), 5 (CN102.1)
PWM_L_0-3: 1 (IC600.2 R558.2), 5 (CN202.1)
PWM_L_0-4: 1 (IC600.5 R559.2), 5 (CN302.1)
STBY_0-1: 1 (IC600.22), 5 (CN3.5)
STBY_0-2: 2 (IC600.85), 5 (CN103.5)
STBY_0-3: 2 (IC600.98), 5 (CN203.5)
STBY_0-4: 3 (IC600.135), 5 (CN303.5)
V_B0-1: 1 (R512.2), 5 (CN2.7)
V_B0-2: 1 (R522.1), 5 (CN102.7)
V_B0-3: 1 (R532.1), 5 (CN202.7)
V_B0-4: 1 (R542.1), 5 (CN302.7)
V_C0-1: 1 (R513.1), 5 (CN2.6)
V_C0-2: 1 (R523.1), 5 (CN102.6)
V_C0-3: 1 (R533.1), 5 (CN202.6)
V_C0-4: 1 (R543.1), 5 (CN302.6)
VP_12R0_SYS: 6 (5 pins), 7 (8 pins), 8 (J802.2)
VP_L_0: 5 (CN3.8), 8 (D801.1)
VP_L_1: 5 (CN103.8), 8 (D802.1)
VP_L_2: 5 (CN203.8), 8 (D803.1)
VP_L_3: 5 (CN303.8), 8 (D804.1)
